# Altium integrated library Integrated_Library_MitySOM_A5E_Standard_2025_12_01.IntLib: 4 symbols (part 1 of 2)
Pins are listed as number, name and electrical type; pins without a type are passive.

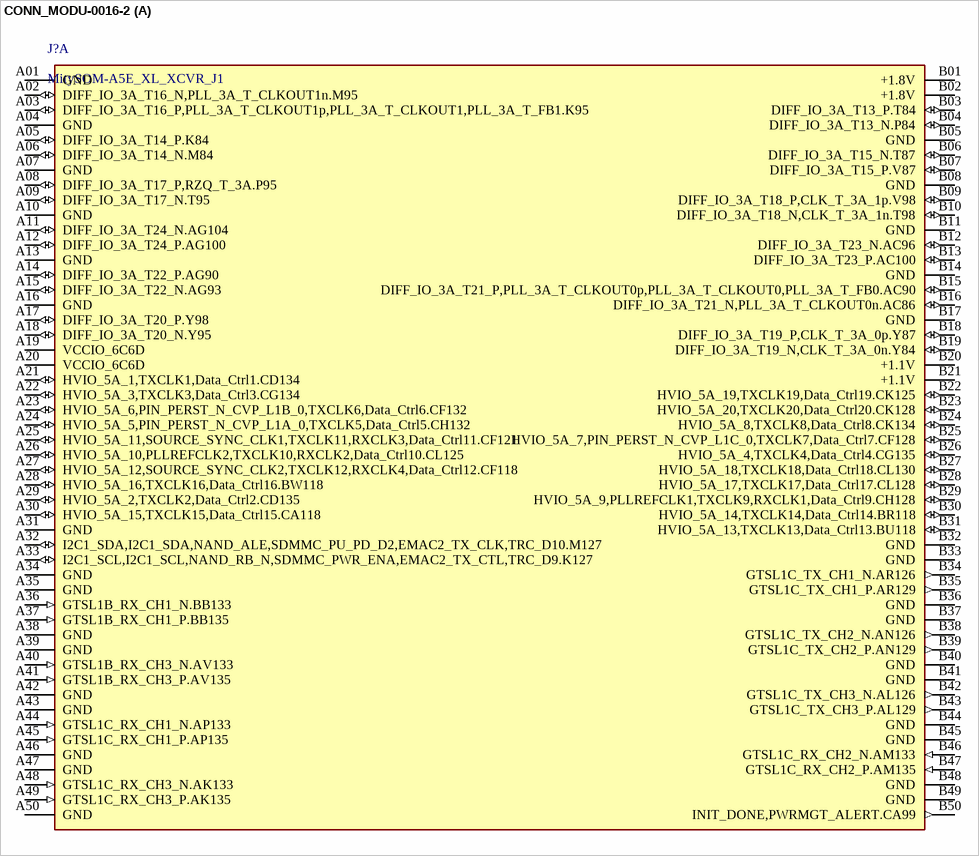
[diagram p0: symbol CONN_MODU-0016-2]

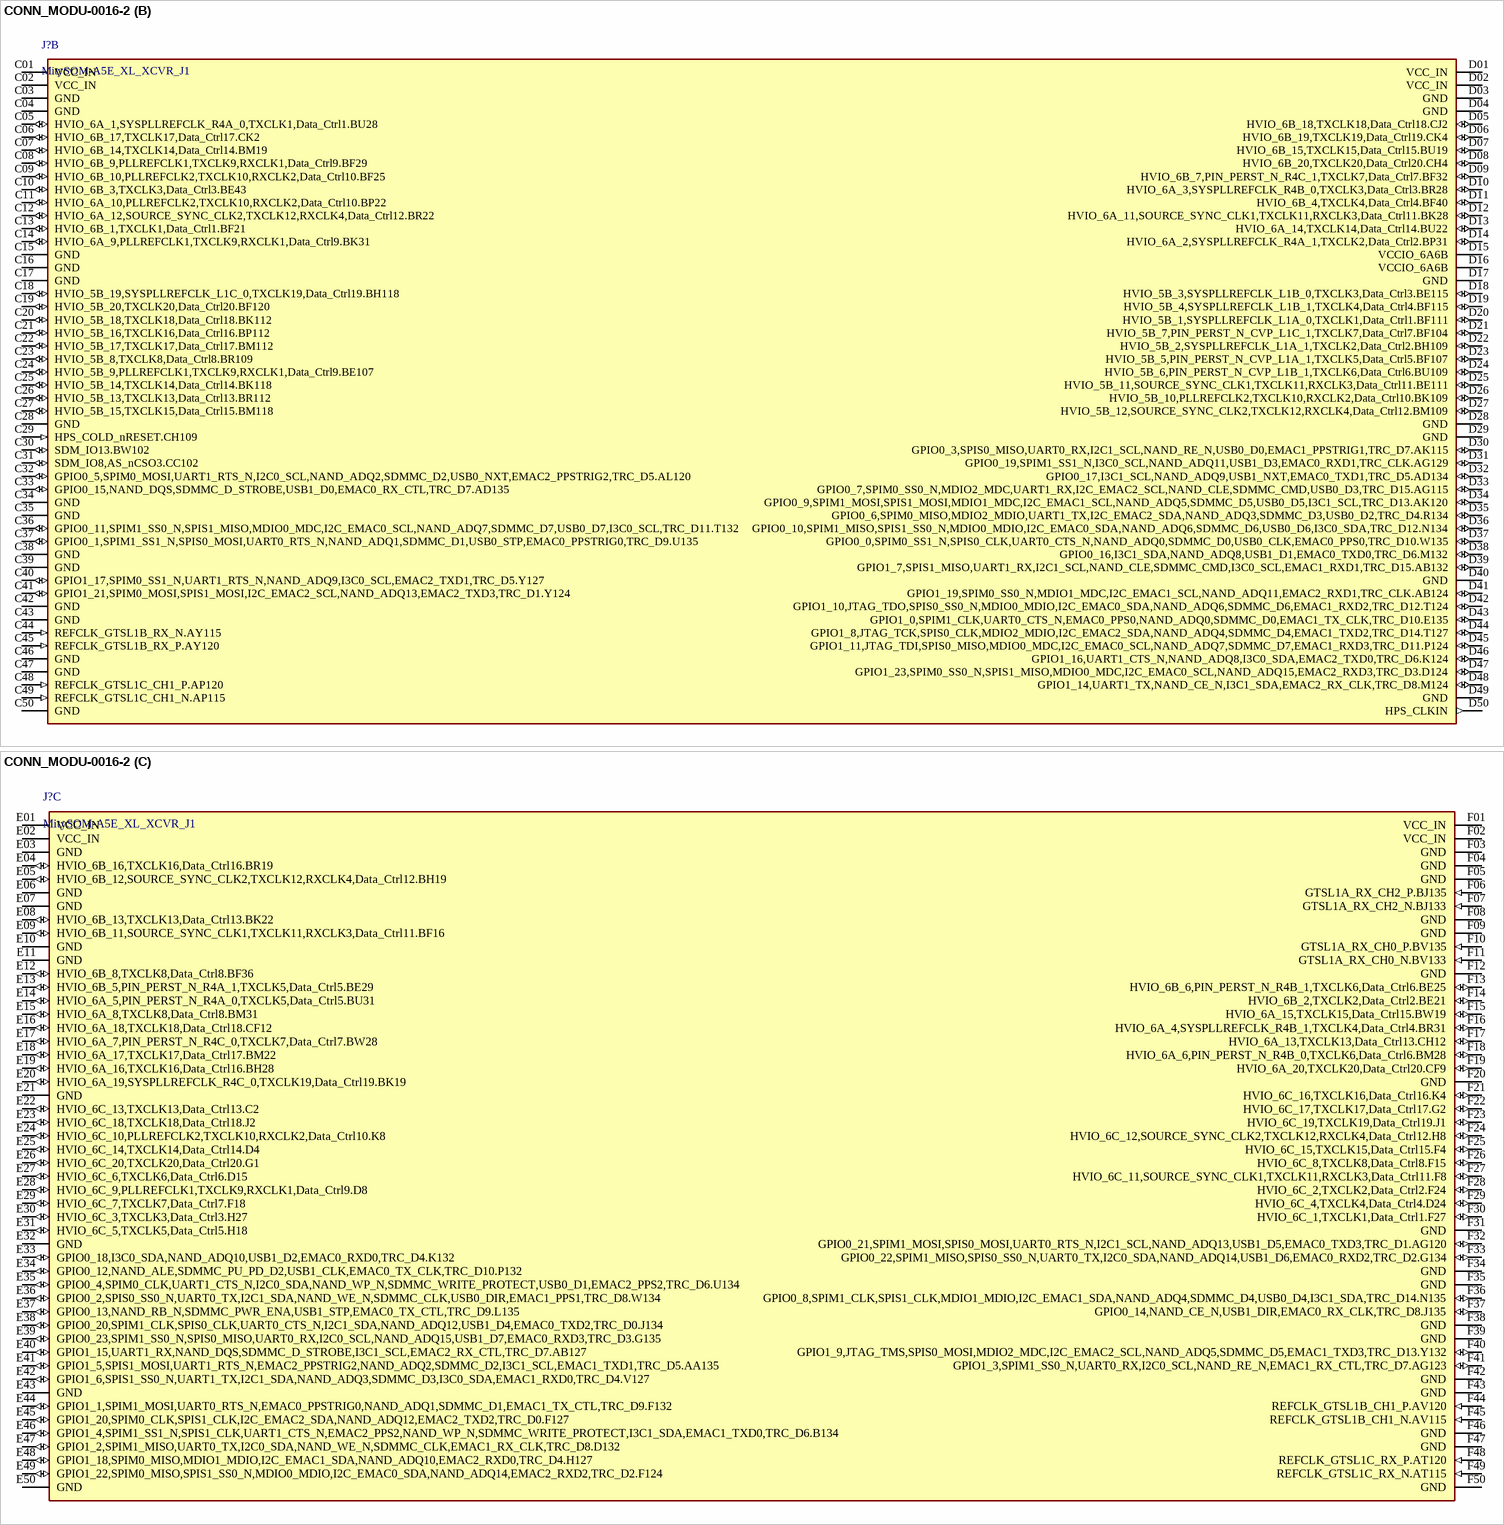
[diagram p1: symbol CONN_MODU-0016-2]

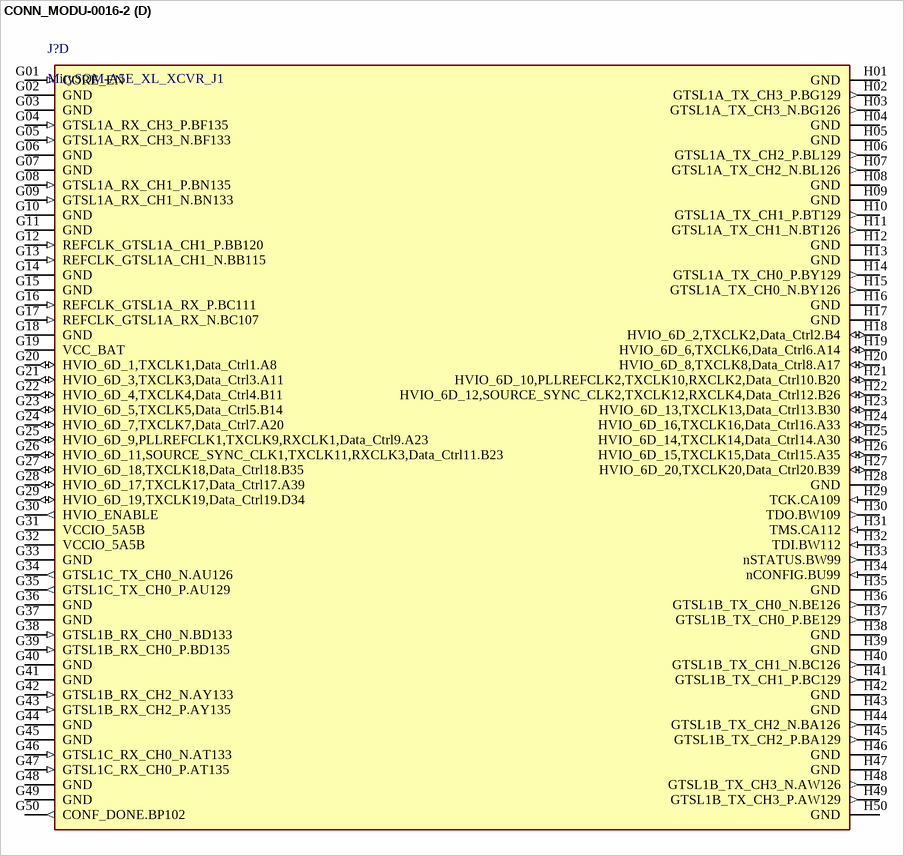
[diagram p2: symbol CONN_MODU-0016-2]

## CONN_MODU-0016-2
designator J?, comment MitySOM-A5E_XL_XCVR_J1
MitySOM-A5E XL XCVR Interface Connector, J1 CONN HD ARRAY PLUG 400P SMD GOLD; Manuf 1_PN: SEAM-50-02.0-L-08-2-A-K-TR; Manuf 2_PN: SEAM-50-02.0-S-08-2-A-K-TR; Manuf 1: Samtec; CLPN: 13059; Angle: Vertical
footprint SEAM-50-02.0-S-08-2-A-K-TR_MitySOM_A5E_J1 (CONN ARRAY SOCKET 400 POS SMD, with mechanical guidelines MitySOM-A5E J1/J2)
part A pins: A01 GND (power), A02 DIFF_IO_3A_T16_N,PLL_3A_T_CLKOUT1n.M95 (io), A03 DIFF_IO_3A_T16_P,PLL_3A_T_CLKOUT1p,PLL_3A_T_CLKOUT1,PLL_3A_T_FB1.K95 (io), A04 GND (power), A05 DIFF_IO_3A_T14_P.K84 (io), A06 DIFF_IO_3A_T14_N.M84 (io), A07 GND (power), A08 DIFF_IO_3A_T17_P,RZQ_T_3A.P95 (io), A09 DIFF_IO_3A_T17_N.T95 (io), A10 GND (power), A11 DIFF_IO_3A_T24_N.AG104 (io), A12 DIFF_IO_3A_T24_P.AG100 (io), A13 GND (power), A14 DIFF_IO_3A_T22_P.AG90 (io), A15 DIFF_IO_3A_T22_N.AG93 (io), A16 GND (power), A17 DIFF_IO_3A_T20_P.Y98 (io), A18 DIFF_IO_3A_T20_N.Y95 (io), A19 VCCIO_6C6D (power), A20 VCCIO_6C6D (power), A21 HVIO_5A_1,TXCLK1,Data_Ctrl1.CD134 (io), A22 HVIO_5A_3,TXCLK3,Data_Ctrl3.CG134 (io), A23 HVIO_5A_6,PIN_PERST_N_CVP_L1B_0,TXCLK6,Data_Ctrl6.CF132 (io), A24 HVIO_5A_5,PIN_PERST_N_CVP_L1A_0,TXCLK5,Data_Ctrl5.CH132 (io), A25 HVIO_5A_11,SOURCE_SYNC_CLK1,TXCLK11,RXCLK3,Data_Ctrl11.CF121 (io), A26 HVIO_5A_10,PLLREFCLK2,TXCLK10,RXCLK2,Data_Ctrl10.CL125 (io), A27 HVIO_5A_12,SOURCE_SYNC_CLK2,TXCLK12,RXCLK4,Data_Ctrl12.CF118 (io), A28 HVIO_5A_16,TXCLK16,Data_Ctrl16.BW118 (io), A29 HVIO_5A_2,TXCLK2,Data_Ctrl2.CD135 (io), A30 HVIO_5A_15,TXCLK15,Data_Ctrl15.CA118 (io), A31 GND (power), A32 I2C1_SDA,I2C1_SDA,NAND_ALE,SDMMC_PU_PD_D2,EMAC2_TX_CLK,TRC_D10.M127 (io), A33 I2C1_SCL,I2C1_SCL,NAND_RB_N,SDMMC_PWR_ENA,EMAC2_TX_CTL,TRC_D9.K127 (io), A34 GND (power), A35 GND (power), A36 GTSL1B_RX_CH1_N.BB133 (in), A37 GTSL1B_RX_CH1_P.BB135 (in), A38 GND (power), A39 GND (power), A40 GTSL1B_RX_CH3_N.AV133 (in), A41 GTSL1B_RX_CH3_P.AV135 (in), A42 GND (power), A43 GND (power), A44 GTSL1C_RX_CH1_N.AP133 (in), A45 GTSL1C_RX_CH1_P.AP135 (in), A46 GND (power), A47 GND (power), A48 GTSL1C_RX_CH3_N.AK133 (in), A49 GTSL1C_RX_CH3_P.AK135 (in), A50 GND (power), B01 +1.8V (power), B02 +1.8V (power), B03 DIFF_IO_3A_T13_P.T84 (io), B04 DIFF_IO_3A_T13_N.P84 (io), B05 GND (power), B06 DIFF_IO_3A_T15_N.T87 (io), B07 DIFF_IO_3A_T15_P.V87 (io), B08 GND (power), B09 DIFF_IO_3A_T18_P,CLK_T_3A_1p.V98 (io), B10 DIFF_IO_3A_T18_N,CLK_T_3A_1n.T98 (io), B11 GND (power), B12 DIFF_IO_3A_T23_N.AC96 (io), B13 DIFF_IO_3A_T23_P.AC100 (io), B14 GND (power), B15 DIFF_IO_3A_T21_P,PLL_3A_T_CLKOUT0p,PLL_3A_T_CLKOUT0,PLL_3A_T_FB0.AC90 (io), B16 DIFF_IO_3A_T21_N,PLL_3A_T_CLKOUT0n.AC86 (io), B17 GND (power), B18 DIFF_IO_3A_T19_P,CLK_T_3A_0p.Y87 (io), B19 DIFF_IO_3A_T19_N,CLK_T_3A_0n.Y84 (io), B20 +1.1V (power), B21 +1.1V (power), B22 HVIO_5A_19,TXCLK19,Data_Ctrl19.CK125 (io), B23 HVIO_5A_20,TXCLK20,Data_Ctrl20.CK128 (io), B24 HVIO_5A_8,TXCLK8,Data_Ctrl8.CK134 (io), B25 HVIO_5A_7,PIN_PERST_N_CVP_L1C_0,TXCLK7,Data_Ctrl7.CF128 (io), B26 HVIO_5A_4,TXCLK4,Data_Ctrl4.CG135 (io), B27 HVIO_5A_18,TXCLK18,Data_Ctrl18.CL130 (io), B28 HVIO_5A_17,TXCLK17,Data_Ctrl17.CL128 (io), B29 HVIO_5A_9,PLLREFCLK1,TXCLK9,RXCLK1,Data_Ctrl9.CH128 (io), B30 HVIO_5A_14,TXCLK14,Data_Ctrl14.BR118 (io), B31 HVIO_5A_13,TXCLK13,Data_Ctrl13.BU118 (io), B32 GND (power), B33 GND (power), B34 GTSL1C_TX_CH1_N.AR126 (out), B35 GTSL1C_TX_CH1_P.AR129 (out), B36 GND (power), B37 GND (power), B38 GTSL1C_TX_CH2_N.AN126 (out), B39 GTSL1C_TX_CH2_P.AN129 (out), B40 GND (power), B41 GND (power), B42 GTSL1C_TX_CH3_N.AL126 (out), B43 GTSL1C_TX_CH3_P.AL129 (out), B44 GND (power), B45 GND (power), B46 GTSL1C_RX_CH2_N.AM133 (in), B47 GTSL1C_RX_CH2_P.AM135 (in), B48 GND (power), B49 GND (power), B50 INIT_DONE,PWRMGT_ALERT.CA99 (out)
part B pins: C01 VCC_IN (power), C02 VCC_IN (power), C03 GND (power), C04 GND (power), C05 HVIO_6A_1,SYSPLLREFCLK_R4A_0,TXCLK1,Data_Ctrl1.BU28 (io), C06 HVIO_6B_17,TXCLK17,Data_Ctrl17.CK2 (io), C07 HVIO_6B_14,TXCLK14,Data_Ctrl14.BM19 (io), C08 HVIO_6B_9,PLLREFCLK1,TXCLK9,RXCLK1,Data_Ctrl9.BF29 (io), C09 HVIO_6B_10,PLLREFCLK2,TXCLK10,RXCLK2,Data_Ctrl10.BF25 (io), C10 HVIO_6B_3,TXCLK3,Data_Ctrl3.BE43 (io), C11 HVIO_6A_10,PLLREFCLK2,TXCLK10,RXCLK2,Data_Ctrl10.BP22 (io), C12 HVIO_6A_12,SOURCE_SYNC_CLK2,TXCLK12,RXCLK4,Data_Ctrl12.BR22 (io), C13 HVIO_6B_1,TXCLK1,Data_Ctrl1.BF21 (io), C14 HVIO_6A_9,PLLREFCLK1,TXCLK9,RXCLK1,Data_Ctrl9.BK31 (io), C15 GND (power), C16 GND (power), C17 GND (power), C18 HVIO_5B_19,SYSPLLREFCLK_L1C_0,TXCLK19,Data_Ctrl19.BH118 (io), C19 HVIO_5B_20,TXCLK20,Data_Ctrl20.BF120 (io), C20 HVIO_5B_18,TXCLK18,Data_Ctrl18.BK112 (io), C21 HVIO_5B_16,TXCLK16,Data_Ctrl16.BP112 (io), C22 HVIO_5B_17,TXCLK17,Data_Ctrl17.BM112 (io), C23 HVIO_5B_8,TXCLK8,Data_Ctrl8.BR109 (io), C24 HVIO_5B_9,PLLREFCLK1,TXCLK9,RXCLK1,Data_Ctrl9.BE107 (io), C25 HVIO_5B_14,TXCLK14,Data_Ctrl14.BK118 (io), C26 HVIO_5B_13,TXCLK13,Data_Ctrl13.BR112 (io), C27 HVIO_5B_15,TXCLK15,Data_Ctrl15.BM118 (io), C28 GND (power), C29 HPS_COLD_nRESET.CH109 (in), C30 SDM_IO13.BW102 (io), C31 SDM_IO8,AS_nCSO3.CC102 (io), C32 GPIO0_5,SPIM0_MOSI,UART1_RTS_N,I2C0_SCL,NAND_ADQ2,SDMMC_D2,USB0_NXT,EMAC2_PPSTRIG2,TRC_D5.AL120 (io), C33 GPIO0_15,NAND_DQS,SDMMC_D_STROBE,USB1_D0,EMAC0_RX_CTL,TRC_D7.AD135 (io), C34 GND (power), C35 GND (power), C36 GPIO0_11,SPIM1_SS0_N,SPIS1_MISO,MDIO0_MDC,I2C_EMAC0_SCL,NAND_ADQ7,SDMMC_D7,USB0_D7,I3C0_SCL,TRC_D11.T132 (io), C37 GPIO0_1,SPIM1_SS1_N,SPIS0_MOSI,UART0_RTS_N,NAND_ADQ1,SDMMC_D1,USB0_STP,EMAC0_PPSTRIG0,TRC_D9.U135 (io), C38 GND (power), C39 GND (power), C40 GPIO1_17,SPIM0_SS1_N,UART1_RTS_N,NAND_ADQ9,I3C0_SCL,EMAC2_TXD1,TRC_D5.Y127 (io), C41 GPIO1_21,SPIM0_MOSI,SPIS1_MOSI,I2C_EMAC2_SCL,NAND_ADQ13,EMAC2_TXD3,TRC_D1.Y124 (io), C42 GND (power), C43 GND (power), C44 REFCLK_GTSL1B_RX_N.AY115 (in), C45 REFCLK_GTSL1B_RX_P.AY120 (in), C46 GND (power), C47 GND (power), C48 REFCLK_GTSL1C_CH1_P.AP120 (in), C49 REFCLK_GTSL1C_CH1_N.AP115 (in), C50 GND (power), D01 VCC_IN (power), D02 VCC_IN (power), D03 GND (power), D04 GND (power), D05 HVIO_6B_18,TXCLK18,Data_Ctrl18.CJ2 (io), D06 HVIO_6B_19,TXCLK19,Data_Ctrl19.CK4 (io), D07 HVIO_6B_15,TXCLK15,Data_Ctrl15.BU19 (io), D08 HVIO_6B_20,TXCLK20,Data_Ctrl20.CH4 (io), D09 HVIO_6B_7,PIN_PERST_N_R4C_1,TXCLK7,Data_Ctrl7.BF32 (io), D10 HVIO_6A_3,SYSPLLREFCLK_R4B_0,TXCLK3,Data_Ctrl3.BR28 (io), D11 HVIO_6B_4,TXCLK4,Data_Ctrl4.BF40 (io), D12 HVIO_6A_11,SOURCE_SYNC_CLK1,TXCLK11,RXCLK3,Data_Ctrl11.BK28 (io), D13 HVIO_6A_14,TXCLK14,Data_Ctrl14.BU22 (io), D14 HVIO_6A_2,SYSPLLREFCLK_R4A_1,TXCLK2,Data_Ctrl2.BP31 (io), D15 VCCIO_6A6B (power), D16 VCCIO_6A6B (power), D17 GND (power), D18 HVIO_5B_3,SYSPLLREFCLK_L1B_0,TXCLK3,Data_Ctrl3.BE115 (io), D19 HVIO_5B_4,SYSPLLREFCLK_L1B_1,TXCLK4,Data_Ctrl4.BF115 (io), D20 HVIO_5B_1,SYSPLLREFCLK_L1A_0,TXCLK1,Data_Ctrl1.BF111 (io), D21 HVIO_5B_7,PIN_PERST_N_CVP_L1C_1,TXCLK7,Data_Ctrl7.BF104 (io), D22 HVIO_5B_2,SYSPLLREFCLK_L1A_1,TXCLK2,Data_Ctrl2.BH109 (io), D23 HVIO_5B_5,PIN_PERST_N_CVP_L1A_1,TXCLK5,Data_Ctrl5.BF107 (io), D24 HVIO_5B_6,PIN_PERST_N_CVP_L1B_1,TXCLK6,Data_Ctrl6.BU109 (io), D25 HVIO_5B_11,SOURCE_SYNC_CLK1,TXCLK11,RXCLK3,Data_Ctrl11.BE111 (io), D26 HVIO_5B_10,PLLREFCLK2,TXCLK10,RXCLK2,Data_Ctrl10.BK109 (io), D27 HVIO_5B_12,SOURCE_SYNC_CLK2,TXCLK12,RXCLK4,Data_Ctrl12.BM109 (io), D28 GND (power), D29 GND (power), D30 GPIO0_3,SPIS0_MISO,UART0_RX,I2C1_SCL,NAND_RE_N,USB0_D0,EMAC1_PPSTRIG1,TRC_D7.AK115 (io), D31 GPIO0_19,SPIM1_SS1_N,I3C0_SCL,NAND_ADQ11,USB1_D3,EMAC0_RXD1,TRC_CLK.AG129 (io), D32 GPIO0_17,I3C1_SCL,NAND_ADQ9,USB1_NXT,EMAC0_TXD1,TRC_D5.AD134 (io), D33 GPIO0_7,SPIM0_SS0_N,MDIO2_MDC,UART1_RX,I2C_EMAC2_SCL,NAND_CLE,SDMMC_CMD,USB0_D3,TRC_D15.AG115 (io), D34 GPIO0_9,SPIM1_MOSI,SPIS1_MOSI,MDIO1_MDC,I2C_EMAC1_SCL,NAND_ADQ5,SDMMC_D5,USB0_D5,I3C1_SCL,TRC_D13.AK120 (io), D35 GPIO0_6,SPIM0_MISO,MDIO2_MDIO,UART1_TX,I2C_EMAC2_SDA,NAND_ADQ3,SDMMC_D3,USB0_D2,TRC_D4.R134 (io), D36 GPIO0_10,SPIM1_MISO,SPIS1_SS0_N,MDIO0_MDIO,I2C_EMAC0_SDA,NAND_ADQ6,SDMMC_D6,USB0_D6,I3C0_SDA,TRC_D12.N134 (io), D37 GPIO0_0,SPIM0_SS1_N,SPIS0_CLK,UART0_CTS_N,NAND_ADQ0,SDMMC_D0,USB0_CLK,EMAC0_PPS0,TRC_D10.W135 (io), D38 GPIO0_16,I3C1_SDA,NAND_ADQ8,USB1_D1,EMAC0_TXD0,TRC_D6.M132 (io), D39 GPIO1_7,SPIS1_MISO,UART1_RX,I2C1_SCL,NAND_CLE,SDMMC_CMD,I3C0_SCL,EMAC1_RXD1,TRC_D15.AB132 (io), D40 GND (power), D41 GPIO1_19,SPIM0_SS0_N,MDIO1_MDC,I2C_EMAC1_SCL,NAND_ADQ11,EMAC2_RXD1,TRC_CLK.AB124 (io), D42 GPIO1_10,JTAG_TDO,SPIS0_SS0_N,MDIO0_MDIO,I2C_EMAC0_SDA,NAND_ADQ6,SDMMC_D6,EMAC1_RXD2,TRC_D12.T124 (io), D43 GPIO1_0,SPIM1_CLK,UART0_CTS_N,EMAC0_PPS0,NAND_ADQ0,SDMMC_D0,EMAC1_TX_CLK,TRC_D10.E135 (io), D44 GPIO1_8,JTAG_TCK,SPIS0_CLK,MDIO2_MDIO,I2C_EMAC2_SDA,NAND_ADQ4,SDMMC_D4,EMAC1_TXD2,TRC_D14.T127 (io), D45 GPIO1_11,JTAG_TDI,SPIS0_MISO,MDIO0_MDC,I2C_EMAC0_SCL,NAND_ADQ7,SDMMC_D7,EMAC1_RXD3,TRC_D11.P124 (io), D46 GPIO1_16,UART1_CTS_N,NAND_ADQ8,I3C0_SDA,EMAC2_TXD0,TRC_D6.K124 (io), D47 GPIO1_23,SPIM0_SS0_N,SPIS1_MISO,MDIO0_MDC,I2C_EMAC0_SCL,NAND_ADQ15,EMAC2_RXD3,TRC_D3.D124 (io), D48 GPIO1_14,UART1_TX,NAND_CE_N,I3C1_SDA,EMAC2_RX_CLK,TRC_D8.M124 (io), D49 GND (power), D50 HPS_CLKIN (out)
part C pins: E01 VCC_IN (power), E02 VCC_IN (power), E03 GND (power), E04 HVIO_6B_16,TXCLK16,Data_Ctrl16.BR19 (io), E05 HVIO_6B_12,SOURCE_SYNC_CLK2,TXCLK12,RXCLK4,Data_Ctrl12.BH19 (io), E06 GND (power), E07 GND (power), E08 HVIO_6B_13,TXCLK13,Data_Ctrl13.BK22 (io), E09 HVIO_6B_11,SOURCE_SYNC_CLK1,TXCLK11,RXCLK3,Data_Ctrl11.BF16 (io), E10 GND (power), E11 GND (power), E12 HVIO_6B_8,TXCLK8,Data_Ctrl8.BF36 (io), E13 HVIO_6B_5,PIN_PERST_N_R4A_1,TXCLK5,Data_Ctrl5.BE29 (io), E14 HVIO_6A_5,PIN_PERST_N_R4A_0,TXCLK5,Data_Ctrl5.BU31 (io), E15 HVIO_6A_8,TXCLK8,Data_Ctrl8.BM31 (io), E16 HVIO_6A_18,TXCLK18,Data_Ctrl18.CF12 (io), E17 HVIO_6A_7,PIN_PERST_N_R4C_0,TXCLK7,Data_Ctrl7.BW28 (io), E18 HVIO_6A_17,TXCLK17,Data_Ctrl17.BM22 (io), E19 HVIO_6A_16,TXCLK16,Data_Ctrl16.BH28 (io), E20 HVIO_6A_19,SYSPLLREFCLK_R4C_0,TXCLK19,Data_Ctrl19.BK19 (io), E21 GND (power), E22 HVIO_6C_13,TXCLK13,Data_Ctrl13.C2 (io), E23 HVIO_6C_18,TXCLK18,Data_Ctrl18.J2 (io), E24 HVIO_6C_10,PLLREFCLK2,TXCLK10,RXCLK2,Data_Ctrl10.K8 (io), E25 HVIO_6C_14,TXCLK14,Data_Ctrl14.D4 (io), E26 HVIO_6C_20,TXCLK20,Data_Ctrl20.G1 (io), E27 HVIO_6C_6,TXCLK6,Data_Ctrl6.D15 (io), E28 HVIO_6C_9,PLLREFCLK1,TXCLK9,RXCLK1,Data_Ctrl9.D8 (io), E29 HVIO_6C_7,TXCLK7,Data_Ctrl7.F18 (io), E30 HVIO_6C_3,TXCLK3,Data_Ctrl3.H27 (io), E31 HVIO_6C_5,TXCLK5,Data_Ctrl5.H18 (io), E32 GND (power), E33 GPIO0_18,I3C0_SDA,NAND_ADQ10,USB1_D2,EMAC0_RXD0,TRC_D4.K132 (io), E34 GPIO0_12,NAND_ALE,SDMMC_PU_PD_D2,USB1_CLK,EMAC0_TX_CLK,TRC_D10.P132 (io), E35 GPIO0_4,SPIM0_CLK,UART1_CTS_N,I2C0_SDA,NAND_WP_N,SDMMC_WRITE_PROTECT,USB0_D1,EMAC2_PPS2,TRC_D6.U134 (io), E36 GPIO0_2,SPIS0_SS0_N,UART0_TX,I2C1_SDA,NAND_WE_N,SDMMC_CLK,USB0_DIR,EMAC1_PPS1,TRC_D8.W134 (io), E37 GPIO0_13,NAND_RB_N,SDMMC_PWR_ENA,USB1_STP,EMAC0_TX_CTL,TRC_D9.L135 (io), E38 GPIO0_20,SPIM1_CLK,SPIS0_CLK,UART0_CTS_N,I2C1_SDA,NAND_ADQ12,USB1_D4,EMAC0_TXD2,TRC_D0.J134 (io), E39 GPIO0_23,SPIM1_SS0_N,SPIS0_MISO,UART0_RX,I2C0_SCL,NAND_ADQ15,USB1_D7,EMAC0_RXD3,TRC_D3.G135 (io), E40 GPIO1_15,UART1_RX,NAND_DQS,SDMMC_D_STROBE,I3C1_SCL,EMAC2_RX_CTL,TRC_D7.AB127 (io), E41 GPIO1_5,SPIS1_MOSI,UART1_RTS_N,EMAC2_PPSTRIG2,NAND_ADQ2,SDMMC_D2,I3C1_SCL,EMAC1_TXD1,TRC_D5.AA135 (io), E42 GPIO1_6,SPIS1_SS0_N,UART1_TX,I2C1_SDA,NAND_ADQ3,SDMMC_D3,I3C0_SDA,EMAC1_RXD0,TRC_D4.V127 (io), E43 GND (power), E44 GPIO1_1,SPIM1_MOSI,UART0_RTS_N,EMAC0_PPSTRIG0,NAND_ADQ1,SDMMC_D1,EMAC1_TX_CTL,TRC_D9.F132 (io), E45 GPIO1_20,SPIM0_CLK,SPIS1_CLK,I2C_EMAC2_SDA,NAND_ADQ12,EMAC2_TXD2,TRC_D0.F127 (io), E46 GPIO1_4,SPIM1_SS1_N,SPIS1_CLK,UART1_CTS_N,EMAC2_PPS2,NAND_WP_N,SDMMC_WRITE_PROTECT,I3C1_SDA,EMAC1_TXD0,TRC_D6.B134 (io), E47 GPIO1_2,SPIM1_MISO,UART0_TX,I2C0_SDA,NAND_WE_N,SDMMC_CLK,EMAC1_RX_CLK,TRC_D8.D132 (io), E48 GPIO1_18,SPIM0_MISO,MDIO1_MDIO,I2C_EMAC1_SDA,NAND_ADQ10,EMAC2_RXD0,TRC_D4.H127 (io), E49 GPIO1_22,SPIM0_MISO,SPIS1_SS0_N,MDIO0_MDIO,I2C_EMAC0_SDA,NAND_ADQ14,EMAC2_RXD2,TRC_D2.F124 (io), E50 GND (power), F01 VCC_IN (power), F02 VCC_IN (power), F03 GND (power), F04 GND (power), F05 GND (power), F06 GTSL1A_RX_CH2_P.BJ135 (in), F07 GTSL1A_RX_CH2_N.BJ133 (in), F08 GND (power), F09 GND (power), F10 GTSL1A_RX_CH0_P.BV135 (in), F11 GTSL1A_RX_CH0_N.BV133 (in), F12 GND (power), F13 HVIO_6B_6,PIN_PERST_N_R4B_1,TXCLK6,Data_Ctrl6.BE25 (io), F14 HVIO_6B_2,TXCLK2,Data_Ctrl2.BE21 (io), F15 HVIO_6A_15,TXCLK15,Data_Ctrl15.BW19 (io), F16 HVIO_6A_4,SYSPLLREFCLK_R4B_1,TXCLK4,Data_Ctrl4.BR31 (io), F17 HVIO_6A_13,TXCLK13,Data_Ctrl13.CH12 (io), F18 HVIO_6A_6,PIN_PERST_N_R4B_0,TXCLK6,Data_Ctrl6.BM28 (io), F19 HVIO_6A_20,TXCLK20,Data_Ctrl20.CF9 (io), F20 GND (power), F21 HVIO_6C_16,TXCLK16,Data_Ctrl16.K4 (io), F22 HVIO_6C_17,TXCLK17,Data_Ctrl17.G2 (io), F23 HVIO_6C_19,TXCLK19,Data_Ctrl19.J1 (io), F24 HVIO_6C_12,SOURCE_SYNC_CLK2,TXCLK12,RXCLK4,Data_Ctrl12.H8 (io), F25 HVIO_6C_15,TXCLK15,Data_Ctrl15.F4 (io), F26 HVIO_6C_8,TXCLK8,Data_Ctrl8.F15 (io), F27 HVIO_6C_11,SOURCE_SYNC_CLK1,TXCLK11,RXCLK3,Data_Ctrl11.F8 (io), F28 HVIO_6C_2,TXCLK2,Data_Ctrl2.F24 (io), F29 HVIO_6C_4,TXCLK4,Data_Ctrl4.D24 (io), F30 HVIO_6C_1,TXCLK1,Data_Ctrl1.F27 (io), F31 GND (power), F32 GPIO0_21,SPIM1_MOSI,SPIS0_MOSI,UART0_RTS_N,I2C1_SCL,NAND_ADQ13,USB1_D5,EMAC0_TXD3,TRC_D1.AG120 (io), F33 GPIO0_22,SPIM1_MISO,SPIS0_SS0_N,UART0_TX,I2C0_SDA,NAND_ADQ14,USB1_D6,EMAC0_RXD2,TRC_D2.G134 (io), F34 GND (power), F35 GND (power), F36 GPIO0_8,SPIM1_CLK,SPIS1_CLK,MDIO1_MDIO,I2C_EMAC1_SDA,NAND_ADQ4,SDMMC_D4,USB0_D4,I3C1_SDA,TRC_D14.N135 (io), F37 GPIO0_14,NAND_CE_N,USB1_DIR,EMAC0_RX_CLK,TRC_D8.J135 (io), F38 GND (power), F39 GND (power), F40 GPIO1_9,JTAG_TMS,SPIS0_MOSI,MDIO2_MDC,I2C_EMAC2_SCL,NAND_ADQ5,SDMMC_D5,EMAC1_TXD3,TRC_D13.Y132 (io), F41 GPIO1_3,SPIM1_SS0_N,UART0_RX,I2C0_SCL,NAND_RE_N,EMAC1_RX_CTL,TRC_D7.AG123 (io), F42 GND (power), F43 GND (power), F44 REFCLK_GTSL1B_CH1_P.AV120 (in), F45 REFCLK_GTSL1B_CH1_N.AV115 (in), F46 GND (power), F47 GND (power), F48 REFCLK_GTSL1C_RX_P.AT120 (in), F49 REFCLK_GTSL1C_RX_N.AT115 (in), F50 GND (power)
part D pins: G01 CORE_EN (in), G02 GND (power), G03 GND (power), G04 GTSL1A_RX_CH3_P.BF135 (in), G05 GTSL1A_RX_CH3_N.BF133 (in), G06 GND (power), G07 GND (power), G08 GTSL1A_RX_CH1_P.BN135 (in), G09 GTSL1A_RX_CH1_N.BN133 (in), G10 GND (power), G11 GND (power), G12 REFCLK_GTSL1A_CH1_P.BB120 (in), G13 REFCLK_GTSL1A_CH1_N.BB115 (in), G14 GND (power), G15 GND (power), G16 REFCLK_GTSL1A_RX_P.BC111 (in), G17 REFCLK_GTSL1A_RX_N.BC107 (in), G18 GND (power), G19 VCC_BAT (power), G20 HVIO_6D_1,TXCLK1,Data_Ctrl1.A8 (io), G21 HVIO_6D_3,TXCLK3,Data_Ctrl3.A11 (io), G22 HVIO_6D_4,TXCLK4,Data_Ctrl4.B11 (io), G23 HVIO_6D_5,TXCLK5,Data_Ctrl5.B14 (io), G24 HVIO_6D_7,TXCLK7,Data_Ctrl7.A20 (io), G25 HVIO_6D_9,PLLREFCLK1,TXCLK9,RXCLK1,Data_Ctrl9.A23 (io), G26 HVIO_6D_11,SOURCE_SYNC_CLK1,TXCLK11,RXCLK3,Data_Ctrl11.B23 (io), G27 HVIO_6D_18,TXCLK18,Data_Ctrl18.B35 (io), G28 HVIO_6D_17,TXCLK17,Data_Ctrl17.A39 (io), G29 HVIO_6D_19,TXCLK19,Data_Ctrl19.D34 (io), G30 HVIO_ENABLE (out), G31 VCCIO_5A5B (power), G32 VCCIO_5A5B (power), G33 GND (power), G34 GTSL1C_TX_CH0_N.AU126 (out), G35 GTSL1C_TX_CH0_P.AU129 (out), G36 GND (power), G37 GND (power), G38 GTSL1B_RX_CH0_N.BD133 (in), G39 GTSL1B_RX_CH0_P.BD135 (in), G40 GND (power), G41 GND (power), G42 GTSL1B_RX_CH2_N.AY133 (in), G43 GTSL1B_RX_CH2_P.AY135 (in), G44 GND (power), G45 GND (power), G46 GTSL1C_RX_CH0_N.AT133 (in), G47 GTSL1C_RX_CH0_P.AT135 (in), G48 GND (power), G49 GND (power), G50 CONF_DONE.BP102 (out), H01 GND (power), H02 GTSL1A_TX_CH3_P.BG129 (out), H03 GTSL1A_TX_CH3_N.BG126 (out), H04 GND (power), H05 GND (power), H06 GTSL1A_TX_CH2_P.BL129 (out), H07 GTSL1A_TX_CH2_N.BL126 (out), H08 GND (power), H09 GND (power), H10 GTSL1A_TX_CH1_P.BT129 (out), H11 GTSL1A_TX_CH1_N.BT126 (out), H12 GND (power), H13 GND (power), H14 GTSL1A_TX_CH0_P.BY129 (out), H15 GTSL1A_TX_CH0_N.BY126 (out), H16 GND (power), H17 GND (power), H18 HVIO_6D_2,TXCLK2,Data_Ctrl2.B4 (io), H19 HVIO_6D_6,TXCLK6,Data_Ctrl6.A14 (io), H20 HVIO_6D_8,TXCLK8,Data_Ctrl8.A17 (io), H21 HVIO_6D_10,PLLREFCLK2,TXCLK10,RXCLK2,Data_Ctrl10.B20 (io), H22 HVIO_6D_12,SOURCE_SYNC_CLK2,TXCLK12,RXCLK4,Data_Ctrl12.B26 (io), H23 HVIO_6D_13,TXCLK13,Data_Ctrl13.B30 (io), H24 HVIO_6D_16,TXCLK16,Data_Ctrl16.A33 (io), H25 HVIO_6D_14,TXCLK14,Data_Ctrl14.A30 (io), H26 HVIO_6D_15,TXCLK15,Data_Ctrl15.A35 (io), H27 HVIO_6D_20,TXCLK20,Data_Ctrl20.B39 (io), H28 GND (power), H29 TCK.CA109 (in), H30 TDO.BW109 (out), H31 TMS.CA112 (in), H32 TDI.BW112 (in), H33 nSTATUS.BW99 (out), H34 nCONFIG.BU99 (in), H35 GND (power), H36 GTSL1B_TX_CH0_N.BE126 (out), H37 GTSL1B_TX_CH0_P.BE129 (out), H38 GND (power), H39 GND (power), H40 GTSL1B_TX_CH1_N.BC126 (out), H41 GTSL1B_TX_CH1_P.BC129 (out), H42 GND (power), H43 GND (power), H44 GTSL1B_TX_CH2_N.BA126 (out), H45 GTSL1B_TX_CH2_P.BA129 (out), H46 GND (power), H47 GND (power), H48 GTSL1B_TX_CH3_N.AW126 (out), H49 GTSL1B_TX_CH3_P.AW129 (out), H50 GND (power)

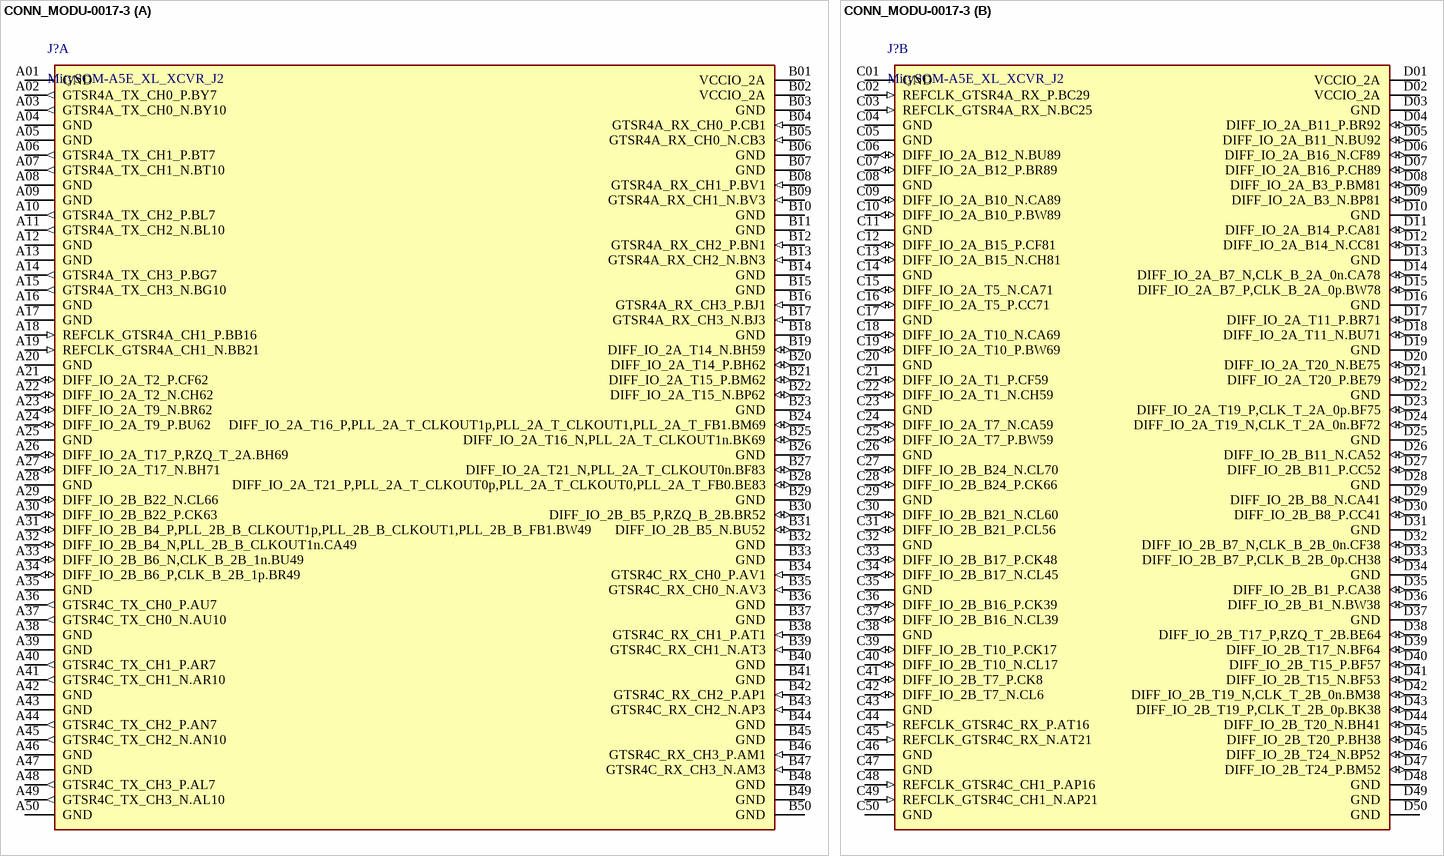
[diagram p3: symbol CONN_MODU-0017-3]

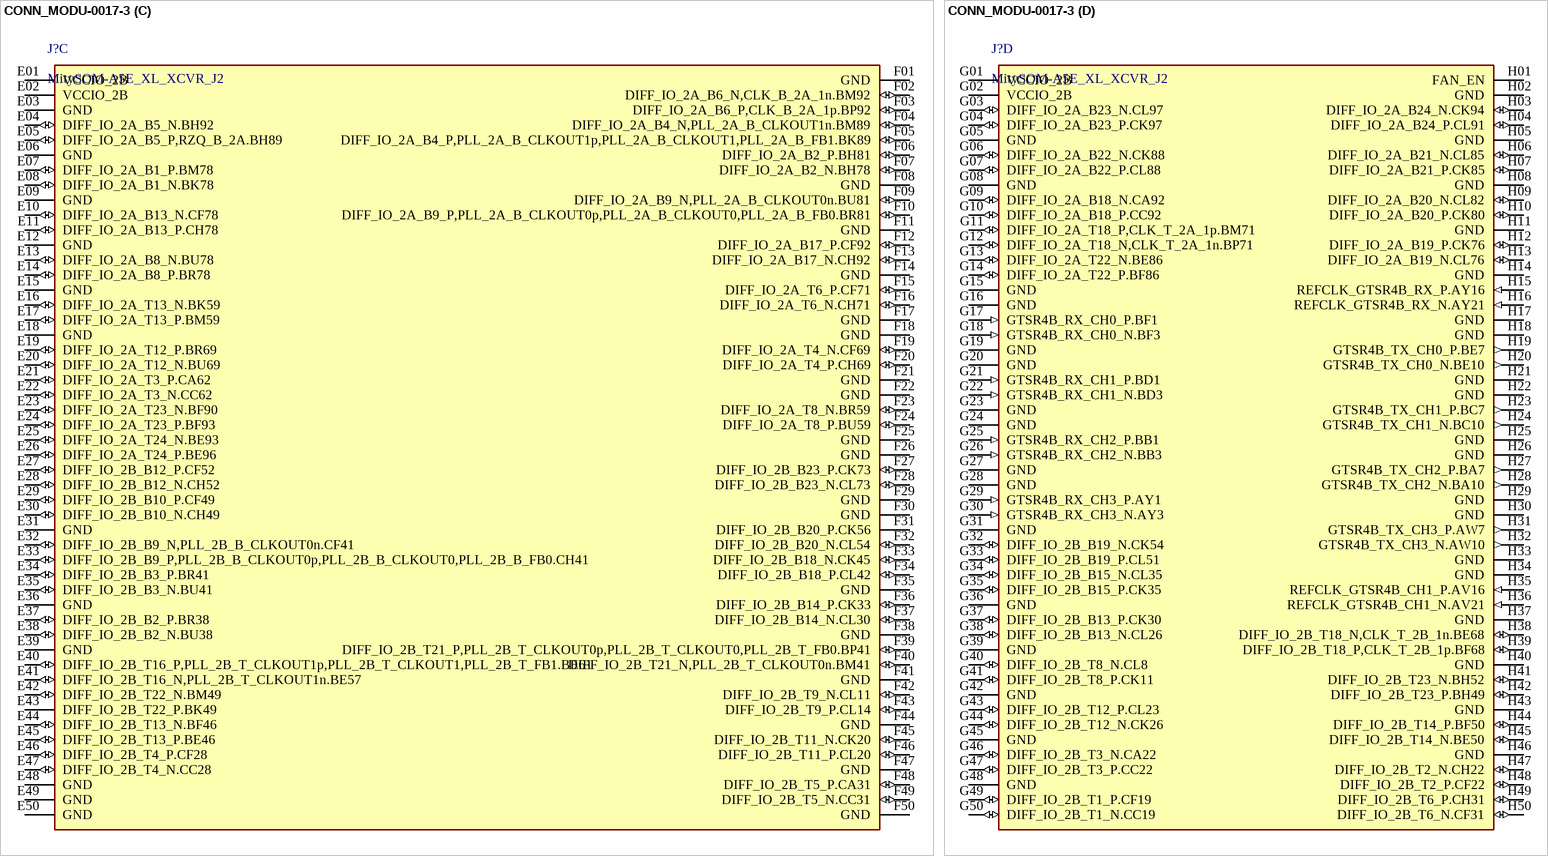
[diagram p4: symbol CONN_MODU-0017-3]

## CONN_MODU-0017-3
designator J?, comment MitySOM-A5E_XL_XCVR_J2
MitySOM-A5E  XL XCVR Interface Connector, J2, CONN HD ARRAY PLUG 400P SMD GOLD; Manuf 1: Samtec; Manuf 1_PN: SEAM-50-02.0-L-08-2-A-K-TR; Manuf 2_PN: SEAM-50-02.0-S-08-2-A-K-TR; Angle: Vertical; CLPN: 13059
footprint SEAM-50-02.0-S-08-2-A-K-TR (CONN ARRAY SOCKET 400 POS SMD)
part A pins: A01 GND (power), A02 GTSR4A_TX_CH0_P.BY7 (out), A03 GTSR4A_TX_CH0_N.BY10 (out), A04 GND (power), A05 GND (power), A06 GTSR4A_TX_CH1_P.BT7 (out), A07 GTSR4A_TX_CH1_N.BT10 (out), A08 GND (power), A09 GND (power), A10 GTSR4A_TX_CH2_P.BL7 (out), A11 GTSR4A_TX_CH2_N.BL10 (out), A12 GND (power), A13 GND (power), A14 GTSR4A_TX_CH3_P.BG7 (out), A15 GTSR4A_TX_CH3_N.BG10 (out), A16 GND (power), A17 GND (power), A18 REFCLK_GTSR4A_CH1_P.BB16 (in), A19 REFCLK_GTSR4A_CH1_N.BB21 (in), A20 GND (power), A21 DIFF_IO_2A_T2_P.CF62 (io), A22 DIFF_IO_2A_T2_N.CH62 (io), A23 DIFF_IO_2A_T9_N.BR62 (io), A24 DIFF_IO_2A_T9_P.BU62 (io), A25 GND (power), A26 DIFF_IO_2A_T17_P,RZQ_T_2A.BH69 (io), A27 DIFF_IO_2A_T17_N.BH71 (io), A28 GND (power), A29 DIFF_IO_2B_B22_N.CL66 (io), A30 DIFF_IO_2B_B22_P.CK63 (io), A31 DIFF_IO_2B_B4_P,PLL_2B_B_CLKOUT1p,PLL_2B_B_CLKOUT1,PLL_2B_B_FB1.BW49 (io), A32 DIFF_IO_2B_B4_N,PLL_2B_B_CLKOUT1n.CA49 (io), A33 DIFF_IO_2B_B6_N,CLK_B_2B_1n.BU49 (io), A34 DIFF_IO_2B_B6_P,CLK_B_2B_1p.BR49 (io), A35 GND (power), A36 GTSR4C_TX_CH0_P.AU7 (out), A37 GTSR4C_TX_CH0_N.AU10 (out), A38 GND (power), A39 GND (power), A40 GTSR4C_TX_CH1_P.AR7 (out), A41 GTSR4C_TX_CH1_N.AR10 (out), A42 GND (power), A43 GND (power), A44 GTSR4C_TX_CH2_P.AN7 (out), A45 GTSR4C_TX_CH2_N.AN10 (out), A46 GND (power), A47 GND (power), A48 GTSR4C_TX_CH3_P.AL7 (out), A49 GTSR4C_TX_CH3_N.AL10 (out), A50 GND (power), B01 VCCIO_2A (power), B02 VCCIO_2A (power), B03 GND (power), B04 GTSR4A_RX_CH0_P.CB1 (in), B05 GTSR4A_RX_CH0_N.CB3 (in), B06 GND (power), B07 GND (power), B08 GTSR4A_RX_CH1_P.BV1 (in), B09 GTSR4A_RX_CH1_N.BV3 (in), B10 GND (power), B11 GND (power), B12 GTSR4A_RX_CH2_P.BN1 (in), B13 GTSR4A_RX_CH2_N.BN3 (in), B14 GND (power), B15 GND (power), B16 GTSR4A_RX_CH3_P.BJ1 (in), B17 GTSR4A_RX_CH3_N.BJ3 (in), B18 GND (power), B19 DIFF_IO_2A_T14_N.BH59 (io), B20 DIFF_IO_2A_T14_P.BH62 (io), B21 DIFF_IO_2A_T15_P.BM62 (io), B22 DIFF_IO_2A_T15_N.BP62 (io), B23 GND (power), B24 DIFF_IO_2A_T16_P,PLL_2A_T_CLKOUT1p,PLL_2A_T_CLKOUT1,PLL_2A_T_FB1.BM69 (io), B25 DIFF_IO_2A_T16_N,PLL_2A_T_CLKOUT1n.BK69 (io), B26 GND (power), B27 DIFF_IO_2A_T21_N,PLL_2A_T_CLKOUT0n.BF83 (io), B28 DIFF_IO_2A_T21_P,PLL_2A_T_CLKOUT0p,PLL_2A_T_CLKOUT0,PLL_2A_T_FB0.BE83 (io), B29 GND (power), B30 DIFF_IO_2B_B5_P,RZQ_B_2B.BR52 (io), B31 DIFF_IO_2B_B5_N.BU52 (io), B32 GND (power), B33 GND (power), B34 GTSR4C_RX_CH0_P.AV1 (in), B35 GTSR4C_RX_CH0_N.AV3 (in), B36 GND (power), B37 GND (power), B38 GTSR4C_RX_CH1_P.AT1 (in), B39 GTSR4C_RX_CH1_N.AT3 (in), B40 GND (power), B41 GND (power), B42 GTSR4C_RX_CH2_P.AP1 (in), B43 GTSR4C_RX_CH2_N.AP3 (in), B44 GND (power), B45 GND (power), B46 GTSR4C_RX_CH3_P.AM1 (in), B47 GTSR4C_RX_CH3_N.AM3 (in), B48 GND (power), B49 GND (power), B50 GND (power)
part B pins: C01 GND (power), C02 REFCLK_GTSR4A_RX_P.BC29 (in), C03 REFCLK_GTSR4A_RX_N.BC25 (in), C04 GND (power), C05 GND (power), C06 DIFF_IO_2A_B12_N.BU89 (io), C07 DIFF_IO_2A_B12_P.BR89 (io), C08 GND (power), C09 DIFF_IO_2A_B10_N.CA89 (io), C10 DIFF_IO_2A_B10_P.BW89 (io), C11 GND (power), C12 DIFF_IO_2A_B15_P.CF81 (io), C13 DIFF_IO_2A_B15_N.CH81 (io), C14 GND (power), C15 DIFF_IO_2A_T5_N.CA71 (io), C16 DIFF_IO_2A_T5_P.CC71 (io), C17 GND (power), C18 DIFF_IO_2A_T10_N.CA69 (io), C19 DIFF_IO_2A_T10_P.BW69 (io), C20 GND (power), C21 DIFF_IO_2A_T1_P.CF59 (io), C22 DIFF_IO_2A_T1_N.CH59 (io), C23 GND (power), C24 DIFF_IO_2A_T7_N.CA59 (io), C25 DIFF_IO_2A_T7_P.BW59 (io), C26 GND (power), C27 DIFF_IO_2B_B24_N.CL70 (io), C28 DIFF_IO_2B_B24_P.CK66 (io), C29 GND (power), C30 DIFF_IO_2B_B21_N.CL60 (io), C31 DIFF_IO_2B_B21_P.CL56 (io), C32 GND (power), C33 DIFF_IO_2B_B17_P.CK48 (io), C34 DIFF_IO_2B_B17_N.CL45 (io), C35 GND (power), C36 DIFF_IO_2B_B16_P.CK39 (io), C37 DIFF_IO_2B_B16_N.CL39 (io), C38 GND (power), C39 DIFF_IO_2B_T10_P.CK17 (io), C40 DIFF_IO_2B_T10_N.CL17 (io), C41 DIFF_IO_2B_T7_P.CK8 (io), C42 DIFF_IO_2B_T7_N.CL6 (io), C43 GND (power), C44 REFCLK_GTSR4C_RX_P.AT16 (in), C45 REFCLK_GTSR4C_RX_N.AT21 (in), C46 GND (power), C47 GND (power), C48 REFCLK_GTSR4C_CH1_P.AP16 (in), C49 REFCLK_GTSR4C_CH1_N.AP21 (in), C50 GND (power), D01 VCCIO_2A (power), D02 VCCIO_2A (power), D03 GND (power), D04 DIFF_IO_2A_B11_P.BR92 (io), D05 DIFF_IO_2A_B11_N.BU92 (io), D06 DIFF_IO_2A_B16_N.CF89 (io), D07 DIFF_IO_2A_B16_P.CH89 (io), D08 DIFF_IO_2A_B3_P.BM81 (io), D09 DIFF_IO_2A_B3_N.BP81 (io), D10 GND (power), D11 DIFF_IO_2A_B14_P.CA81 (io), D12 DIFF_IO_2A_B14_N.CC81 (io), D13 GND (power), D14 DIFF_IO_2A_B7_N,CLK_B_2A_0n.CA78 (io), D15 DIFF_IO_2A_B7_P,CLK_B_2A_0p.BW78 (io), D16 GND (power), D17 DIFF_IO_2A_T11_P.BR71 (io), D18 DIFF_IO_2A_T11_N.BU71 (io), D19 GND (power), D20 DIFF_IO_2A_T20_N.BE75 (io), D21 DIFF_IO_2A_T20_P.BE79 (io), D22 GND (power), D23 DIFF_IO_2A_T19_P,CLK_T_2A_0p.BF75 (io), D24 DIFF_IO_2A_T19_N,CLK_T_2A_0n.BF72 (io), D25 GND (power), D26 DIFF_IO_2B_B11_N.CA52 (io), D27 DIFF_IO_2B_B11_P.CC52 (io), D28 GND (power), D29 DIFF_IO_2B_B8_N.CA41 (io), D30 DIFF_IO_2B_B8_P.CC41 (io), D31 GND (power), D32 DIFF_IO_2B_B7_N,CLK_B_2B_0n.CF38 (io), D33 DIFF_IO_2B_B7_P,CLK_B_2B_0p.CH38 (io), D34 GND (power), D35 DIFF_IO_2B_B1_P.CA38 (io), D36 DIFF_IO_2B_B1_N.BW38 (io), D37 GND (power), D38 DIFF_IO_2B_T17_P,RZQ_T_2B.BE64 (io), D39 DIFF_IO_2B_T17_N.BF64 (io), D40 DIFF_IO_2B_T15_P.BF57 (io), D41 DIFF_IO_2B_T15_N.BF53 (io), D42 DIFF_IO_2B_T19_N,CLK_T_2B_0n.BM38 (io), D43 DIFF_IO_2B_T19_P,CLK_T_2B_0p.BK38 (io), D44 DIFF_IO_2B_T20_N.BH41 (io), D45 DIFF_IO_2B_T20_P.BH38 (io), D46 DIFF_IO_2B_T24_N.BP52 (io), D47 DIFF_IO_2B_T24_P.BM52 (io), D48 GND (power), D49 GND (power), D50 GND (power)
part C pins: E01 VCCIO_2B (power), E02 VCCIO_2B (power), E03 GND (power), E04 DIFF_IO_2A_B5_N.BH92 (io), E05 DIFF_IO_2A_B5_P,RZQ_B_2A.BH89 (io), E06 GND (power), E07 DIFF_IO_2A_B1_P.BM78 (io), E08 DIFF_IO_2A_B1_N.BK78 (io), E09 GND (power), E10 DIFF_IO_2A_B13_N.CF78 (io), E11 DIFF_IO_2A_B13_P.CH78 (io), E12 GND (power), E13 DIFF_IO_2A_B8_N.BU78 (io), E14 DIFF_IO_2A_B8_P.BR78 (io), E15 GND (power), E16 DIFF_IO_2A_T13_N.BK59 (io), E17 DIFF_IO_2A_T13_P.BM59 (io), E18 GND (power), E19 DIFF_IO_2A_T12_P.BR69 (io), E20 DIFF_IO_2A_T12_N.BU69 (io), E21 DIFF_IO_2A_T3_P.CA62 (io), E22 DIFF_IO_2A_T3_N.CC62 (io), E23 DIFF_IO_2A_T23_N.BF90 (io), E24 DIFF_IO_2A_T23_P.BF93 (io), E25 DIFF_IO_2A_T24_N.BE93 (io), E26 DIFF_IO_2A_T24_P.BE96 (io), E27 DIFF_IO_2B_B12_P.CF52 (io), E28 DIFF_IO_2B_B12_N.CH52 (io), E29 DIFF_IO_2B_B10_P.CF49 (io), E30 DIFF_IO_2B_B10_N.CH49 (io), E31 GND (power), E32 DIFF_IO_2B_B9_N,PLL_2B_B_CLKOUT0n.CF41 (io), E33 DIFF_IO_2B_B9_P,PLL_2B_B_CLKOUT0p,PLL_2B_B_CLKOUT0,PLL_2B_B_FB0.CH41 (io), E34 DIFF_IO_2B_B3_P.BR41 (io), E35 DIFF_IO_2B_B3_N.BU41 (io), E36 GND (power), E37 DIFF_IO_2B_B2_P.BR38 (io), E38 DIFF_IO_2B_B2_N.BU38 (io), E39 GND (power), E40 DIFF_IO_2B_T16_P,PLL_2B_T_CLKOUT1p,PLL_2B_T_CLKOUT1,PLL_2B_T_FB1.BE61 (io), E41 DIFF_IO_2B_T16_N,PLL_2B_T_CLKOUT1n.BE57 (io), E42 DIFF_IO_2B_T22_N.BM49 (io), E43 DIFF_IO_2B_T22_P.BK49 (power), E44 DIFF_IO_2B_T13_N.BF46 (io), E45 DIFF_IO_2B_T13_P.BE46 (io), E46 DIFF_IO_2B_T4_P.CF28 (io), E47 DIFF_IO_2B_T4_N.CC28 (io), E48 GND (power), E49 GND (power), E50 GND (power), F01 GND (power), F02 DIFF_IO_2A_B6_N,CLK_B_2A_1n.BM92 (io), F03 DIFF_IO_2A_B6_P,CLK_B_2A_1p.BP92 (io), F04 DIFF_IO_2A_B4_N,PLL_2A_B_CLKOUT1n.BM89 (io), F05 DIFF_IO_2A_B4_P,PLL_2A_B_CLKOUT1p,PLL_2A_B_CLKOUT1,PLL_2A_B_FB1.BK89 (io), F06 DIFF_IO_2A_B2_P.BH81 (io), F07 DIFF_IO_2A_B2_N.BH78 (io), F08 GND (power), F09 DIFF_IO_2A_B9_N,PLL_2A_B_CLKOUT0n.BU81 (io), F10 DIFF_IO_2A_B9_P,PLL_2A_B_CLKOUT0p,PLL_2A_B_CLKOUT0,PLL_2A_B_FB0.BR81 (io), F11 GND (power), F12 DIFF_IO_2A_B17_P.CF92 (io), F13 DIFF_IO_2A_B17_N.CH92 (io), F14 GND (power), F15 DIFF_IO_2A_T6_P.CF71 (io), F16 DIFF_IO_2A_T6_N.CH71 (io), F17 GND (power), F18 GND (power), F19 DIFF_IO_2A_T4_N.CF69 (io), F20 DIFF_IO_2A_T4_P.CH69 (io), F21 GND (power), F22 GND (power), F23 DIFF_IO_2A_T8_N.BR59 (io), F24 DIFF_IO_2A_T8_P.BU59 (io), F25 GND (power), F26 GND (power), F27 DIFF_IO_2B_B23_P.CK73 (io), F28 DIFF_IO_2B_B23_N.CL73 (io), F29 GND (power), F30 GND (power), F31 DIFF_IO_2B_B20_P.CK56 (power), F32 DIFF_IO_2B_B20_N.CL54 (io), F33 DIFF_IO_2B_B18_N.CK45 (io), F34 DIFF_IO_2B_B18_P.CL42 (io), F35 GND (power), F36 DIFF_IO_2B_B14_P.CK33 (io), F37 DIFF_IO_2B_B14_N.CL30 (io), F38 GND (power), F39 DIFF_IO_2B_T21_P,PLL_2B_T_CLKOUT0p,PLL_2B_T_CLKOUT0,PLL_2B_T_FB0.BP41 (io), F40 DIFF_IO_2B_T21_N,PLL_2B_T_CLKOUT0n.BM41 (io), F41 GND (power), F42 DIFF_IO_2B_T9_N.CL11 (io), F43 DIFF_IO_2B_T9_P.CL14 (io), F44 GND (power), F45 DIFF_IO_2B_T11_N.CK20 (io), F46 DIFF_IO_2B_T11_P.CL20 (io), F47 GND (power), F48 DIFF_IO_2B_T5_P.CA31 (io), F49 DIFF_IO_2B_T5_N.CC31 (io), F50 GND (power)
part D pins: G01 VCCIO_2B (power), G02 VCCIO_2B (power), G03 DIFF_IO_2A_B23_N.CL97 (io), G04 DIFF_IO_2A_B23_P.CK97 (io), G05 GND (power), G06 DIFF_IO_2A_B22_N.CK88 (io), G07 DIFF_IO_2A_B22_P.CL88 (io), G08 GND (power), G09 DIFF_IO_2A_B18_N.CA92 (io), G10 DIFF_IO_2A_B18_P.CC92 (io), G11 DIFF_IO_2A_T18_P,CLK_T_2A_1p.BM71 (io), G12 DIFF_IO_2A_T18_N,CLK_T_2A_1n.BP71 (io), G13 DIFF_IO_2A_T22_N.BE86 (io), G14 DIFF_IO_2A_T22_P.BF86 (io), G15 GND (power), G16 GND (power), G17 GTSR4B_RX_CH0_P.BF1 (in), G18 GTSR4B_RX_CH0_N.BF3 (in), G19 GND (power), G20 GND (power), G21 GTSR4B_RX_CH1_P.BD1 (in), G22 GTSR4B_RX_CH1_N.BD3 (in), G23 GND (power), G24 GND (power), G25 GTSR4B_RX_CH2_P.BB1 (in), G26 GTSR4B_RX_CH2_N.BB3 (in), G27 GND (power), G28 GND (power), G29 GTSR4B_RX_CH3_P.AY1 (in), G30 GTSR4B_RX_CH3_N.AY3 (in), G31 GND (power), G32 DIFF_IO_2B_B19_N.CK54 (io), G33 DIFF_IO_2B_B19_P.CL51 (io), G34 DIFF_IO_2B_B15_N.CL35 (io), G35 DIFF_IO_2B_B15_P.CK35 (io), G36 GND (power), G37 DIFF_IO_2B_B13_P.CK30 (io), G38 DIFF_IO_2B_B13_N.CL26 (io), G39 GND (power), G40 DIFF_IO_2B_T8_N.CL8 (io), G41 DIFF_IO_2B_T8_P.CK11 (io), G42 GND (power), G43 DIFF_IO_2B_T12_P.CL23 (io), G44 DIFF_IO_2B_T12_N.CK26 (io), G45 GND (power), G46 DIFF_IO_2B_T3_N.CA22 (io), G47 DIFF_IO_2B_T3_P.CC22 (io), G48 GND (power), G49 DIFF_IO_2B_T1_P.CF19 (io), G50 DIFF_IO_2B_T1_N.CC19 (io), H01 FAN_EN (power), H02 GND (power), H03 DIFF_IO_2A_B24_N.CK94 (io), H04 DIFF_IO_2A_B24_P.CL91 (io), H05 GND (power), H06 DIFF_IO_2A_B21_N.CL85 (io), H07 DIFF_IO_2A_B21_P.CK85 (io), H08 GND (power), H09 DIFF_IO_2A_B20_N.CL82 (io), H10 DIFF_IO_2A_B20_P.CK80 (io), H11 GND (power), H12 DIFF_IO_2A_B19_P.CK76 (io), H13 DIFF_IO_2A_B19_N.CL76 (io), H14 GND (power), H15 REFCLK_GTSR4B_RX_P.AY16 (in), H16 REFCLK_GTSR4B_RX_N.AY21 (in), H17 GND (power), H18 GND (power), H19 GTSR4B_TX_CH0_P.BE7 (out), H20 GTSR4B_TX_CH0_N.BE10 (out), H21 GND (power), H22 GND (power), H23 GTSR4B_TX_CH1_P.BC7 (out), H24 GTSR4B_TX_CH1_N.BC10 (out), H25 GND (power), H26 GND (power), H27 GTSR4B_TX_CH2_P.BA7 (out), H28 GTSR4B_TX_CH2_N.BA10 (out), H29 GND (power), H30 GND (power), H31 GTSR4B_TX_CH3_P.AW7 (out), H32 GTSR4B_TX_CH3_N.AW10 (out), H33 GND (power), H34 GND (power), H35 REFCLK_GTSR4B_CH1_P.AV16 (in), H36 REFCLK_GTSR4B_CH1_N.AV21 (in), H37 GND (power), H38 DIFF_IO_2B_T18_N,CLK_T_2B_1n.BE68 (io), H39 DIFF_IO_2B_T18_P,CLK_T_2B_1p.BF68 (io), H40 GND (power), H41 DIFF_IO_2B_T23_N.BH52 (io), H42 DIFF_IO_2B_T23_P.BH49 (io), H43 GND (power), H44 DIFF_IO_2B_T14_P.BF50 (io), H45 DIFF_IO_2B_T14_N.BE50 (io), H46 GND (power), H47 DIFF_IO_2B_T2_N.CH22 (io), H48 DIFF_IO_2B_T2_P.CF22 (io), H49 DIFF_IO_2B_T6_P.CH31 (io), H50 DIFF_IO_2B_T6_N.CF31 (io)

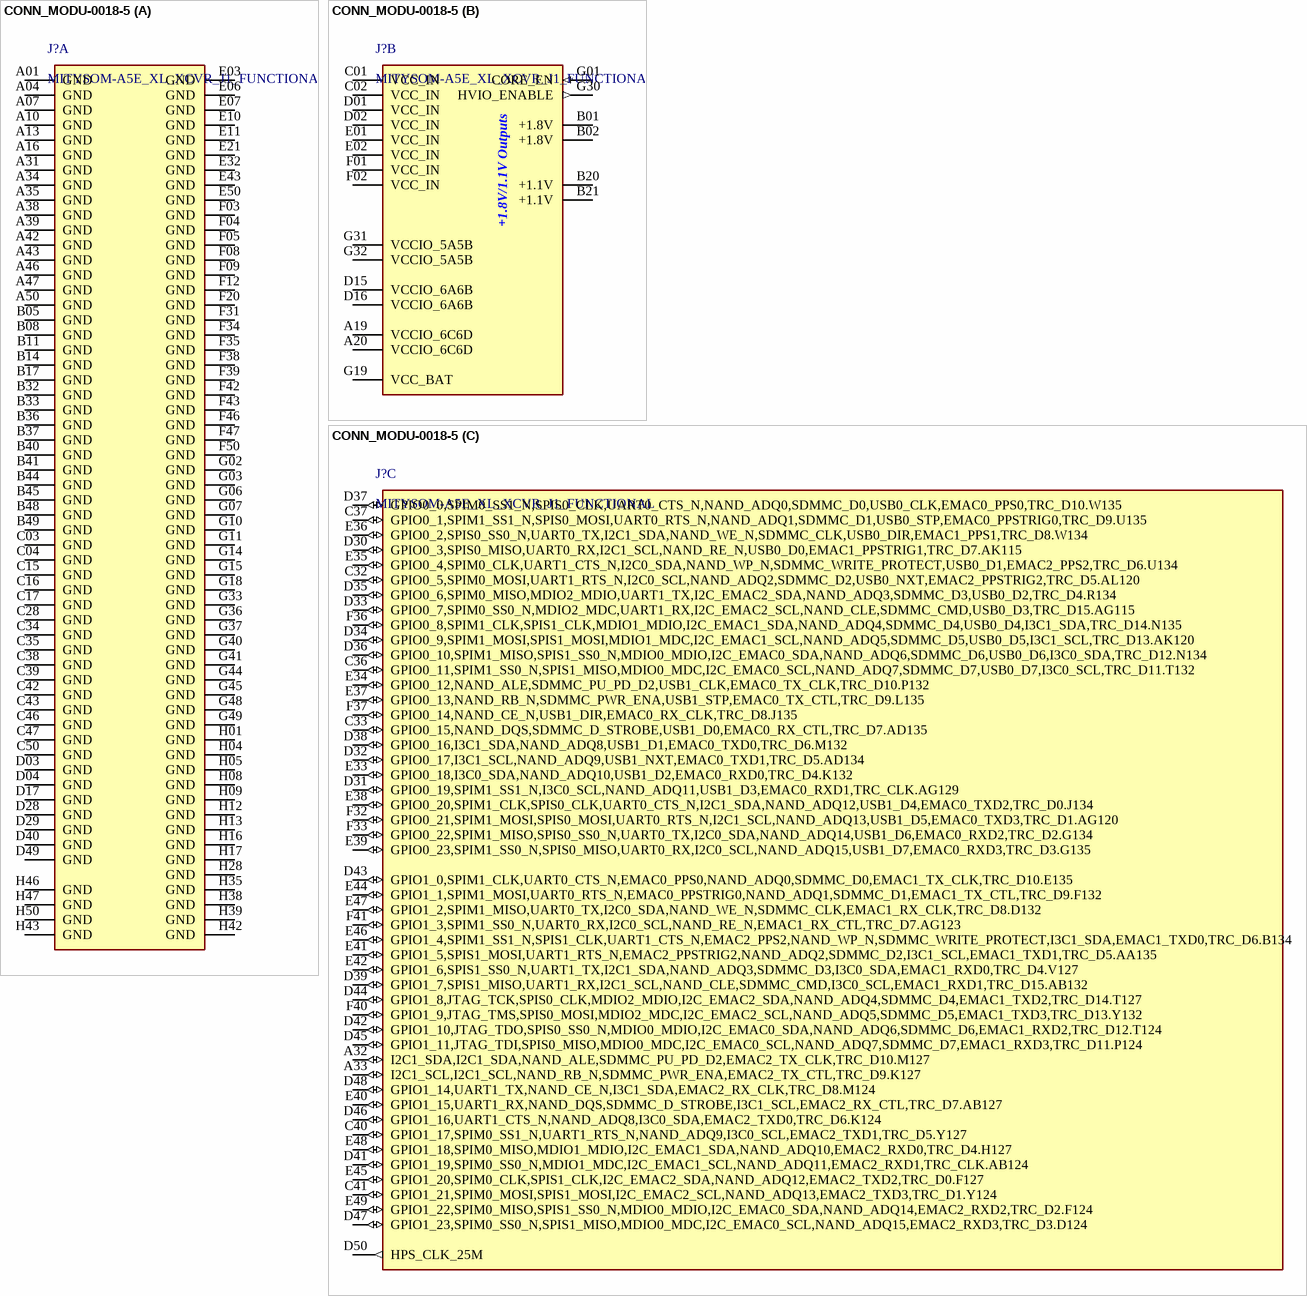
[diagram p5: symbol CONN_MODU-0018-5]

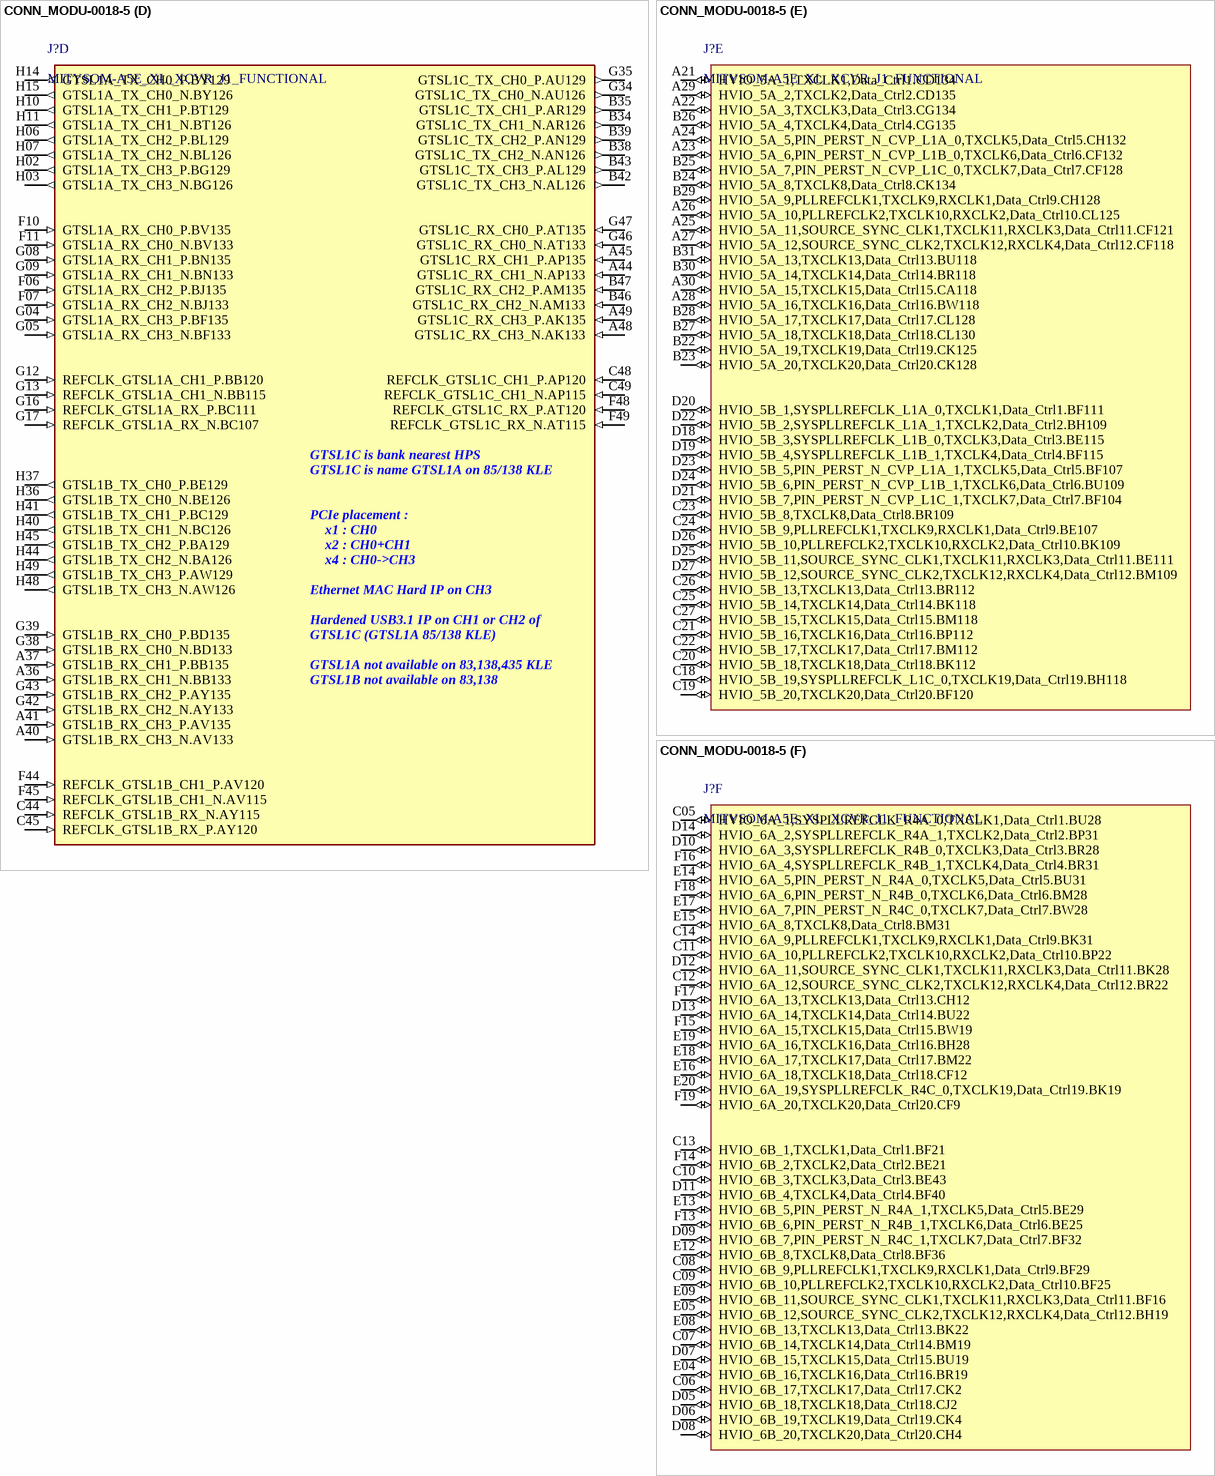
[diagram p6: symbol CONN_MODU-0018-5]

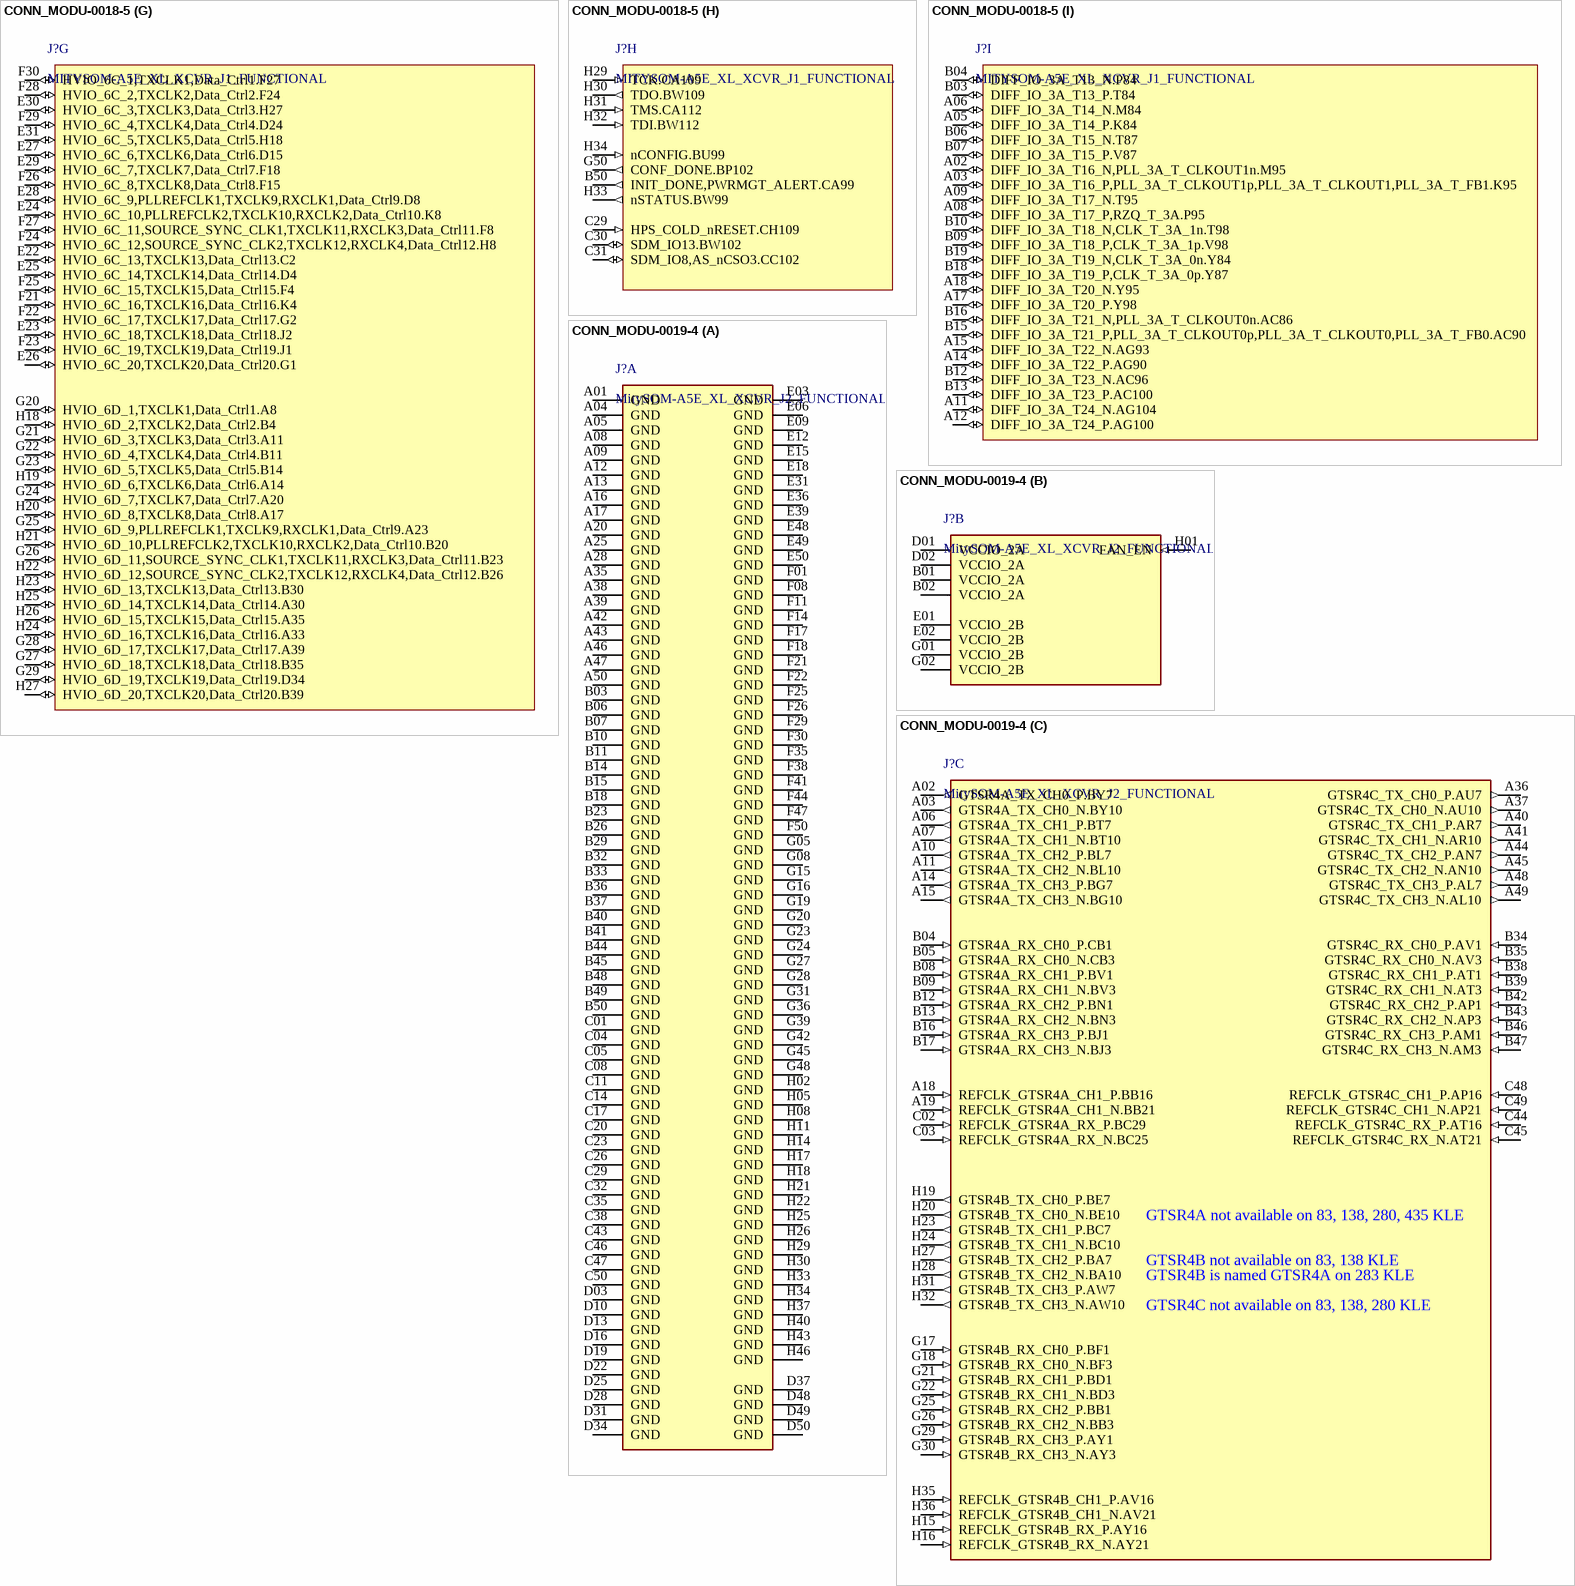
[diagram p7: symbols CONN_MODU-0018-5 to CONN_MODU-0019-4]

## CONN_MODU-0018-5
designator J?, comment MITYSOM-A5E_XL_XCVR_J1_FUNCTIONAL
MitySOM-A5E XL XCVR Interface Connector, J1 CONN HD ARRAY PLUG 400P SMD GOLD; Manuf 1_PN: SEAM-50-02.0-L-08-2-A-K-TR; Manuf 2_PN: SEAM-50-02.0-S-08-2-A-K-TR; Manuf 1: Samtec; Angle: Vertical; CLPN: 13059
footprint SEAM-50-02.0-S-08-2-A-K-TR_MitySOM_A5E_J1 (CONN ARRAY SOCKET 400 POS SMD, with mechanical guidelines MitySOM-A5E J1/J2)
part A pins: A01 GND (power), A04 GND (power), A07 GND (power), A10 GND (power), A13 GND (power), A16 GND (power), A31 GND (power), A34 GND (power), A35 GND (power), A38 GND (power), A39 GND (power), A42 GND (power), A43 GND (power), A46 GND (power), A47 GND (power), A50 GND (power), B05 GND (power), B08 GND (power), B11 GND (power), B14 GND (power), B17 GND (power), B32 GND (power), B33 GND (power), B36 GND (power), B37 GND (power), B40 GND (power), B41 GND (power), B44 GND (power), B45 GND (power), B48 GND (power), B49 GND (power), C03 GND (power), C04 GND (power), C15 GND (power), C16 GND (power), C17 GND (power), C28 GND (power), C34 GND (power), C35 GND (power), C38 GND (power), C39 GND (power), C42 GND (power), C43 GND (power), C46 GND (power), C47 GND (power), C50 GND (power), D03 GND (power), D04 GND (power), D17 GND (power), D28 GND (power), D29 GND (power), D40 GND (power), D49 GND (power), E03 GND (power), E06 GND (power), E07 GND (power), E10 GND (power), E11 GND (power), E21 GND (power), E32 GND (power), E43 GND (power), E50 GND (power), F03 GND (power), F04 GND (power), F05 GND (power), F08 GND (power), F09 GND (power), F12 GND (power), F20 GND (power), F31 GND (power), F34 GND (power), F35 GND (power), F38 GND (power), F39 GND (power), F42 GND (power), F43 GND (power), F46 GND (power), F47 GND (power), F50 GND (power), G02 GND (power), G03 GND (power), G06 GND (power), G07 GND (power), G10 GND (power), G11 GND (power), G14 GND (power), G15 GND (power), G18 GND (power), G33 GND (power), G36 GND (power), G37 GND (power), G40 GND (power), G41 GND (power), G44 GND (power), G45 GND (power), G48 GND (power), G49 GND (power), H01 GND (power), H04 GND (power), H05 GND (power), H08 GND (power), H09 GND (power), H12 GND (power), H13 GND (power), H16 GND (power), H17 GND (power), H28 GND (power), H35 GND (power), H38 GND (power), H39 GND (power), H42 GND (power), H43 GND (power), H46 GND (power), H47 GND (power), H50 GND (power)
part B pins: A19 VCCIO_6C6D (power), A20 VCCIO_6C6D (power), B01 +1.8V (power), B02 +1.8V (power), B20 +1.1V (power), B21 +1.1V (power), C01 VCC_IN (power), C02 VCC_IN (power), D01 VCC_IN (power), D02 VCC_IN (power), D15 VCCIO_6A6B (power), D16 VCCIO_6A6B (power), E01 VCC_IN (power), E02 VCC_IN (power), F01 VCC_IN (power), F02 VCC_IN (power), G01 CORE_EN (in), G19 VCC_BAT (power), G30 HVIO_ENABLE (out), G31 VCCIO_5A5B (power), G32 VCCIO_5A5B (power)
part C pins: A32 I2C1_SDA,I2C1_SDA,NAND_ALE,SDMMC_PU_PD_D2,EMAC2_TX_CLK,TRC_D10.M127 (io), A33 I2C1_SCL,I2C1_SCL,NAND_RB_N,SDMMC_PWR_ENA,EMAC2_TX_CTL,TRC_D9.K127 (io), C32 GPIO0_5,SPIM0_MOSI,UART1_RTS_N,I2C0_SCL,NAND_ADQ2,SDMMC_D2,USB0_NXT,EMAC2_PPSTRIG2,TRC_D5.AL120 (io), C33 GPIO0_15,NAND_DQS,SDMMC_D_STROBE,USB1_D0,EMAC0_RX_CTL,TRC_D7.AD135 (io), C36 GPIO0_11,SPIM1_SS0_N,SPIS1_MISO,MDIO0_MDC,I2C_EMAC0_SCL,NAND_ADQ7,SDMMC_D7,USB0_D7,I3C0_SCL,TRC_D11.T132 (io), C37 GPIO0_1,SPIM1_SS1_N,SPIS0_MOSI,UART0_RTS_N,NAND_ADQ1,SDMMC_D1,USB0_STP,EMAC0_PPSTRIG0,TRC_D9.U135 (io), C40 GPIO1_17,SPIM0_SS1_N,UART1_RTS_N,NAND_ADQ9,I3C0_SCL,EMAC2_TXD1,TRC_D5.Y127 (io), C41 GPIO1_21,SPIM0_MOSI,SPIS1_MOSI,I2C_EMAC2_SCL,NAND_ADQ13,EMAC2_TXD3,TRC_D1.Y124 (io), D30 GPIO0_3,SPIS0_MISO,UART0_RX,I2C1_SCL,NAND_RE_N,USB0_D0,EMAC1_PPSTRIG1,TRC_D7.AK115 (io), D31 GPIO0_19,SPIM1_SS1_N,I3C0_SCL,NAND_ADQ11,USB1_D3,EMAC0_RXD1,TRC_CLK.AG129 (io), D32 GPIO0_17,I3C1_SCL,NAND_ADQ9,USB1_NXT,EMAC0_TXD1,TRC_D5.AD134 (io), D33 GPIO0_7,SPIM0_SS0_N,MDIO2_MDC,UART1_RX,I2C_EMAC2_SCL,NAND_CLE,SDMMC_CMD,USB0_D3,TRC_D15.AG115 (io), D34 GPIO0_9,SPIM1_MOSI,SPIS1_MOSI,MDIO1_MDC,I2C_EMAC1_SCL,NAND_ADQ5,SDMMC_D5,USB0_D5,I3C1_SCL,TRC_D13.AK120 (io), D35 GPIO0_6,SPIM0_MISO,MDIO2_MDIO,UART1_TX,I2C_EMAC2_SDA,NAND_ADQ3,SDMMC_D3,USB0_D2,TRC_D4.R134 (io), D36 GPIO0_10,SPIM1_MISO,SPIS1_SS0_N,MDIO0_MDIO,I2C_EMAC0_SDA,NAND_ADQ6,SDMMC_D6,USB0_D6,I3C0_SDA,TRC_D12.N134 (io), D37 GPIO0_0,SPIM0_SS1_N,SPIS0_CLK,UART0_CTS_N,NAND_ADQ0,SDMMC_D0,USB0_CLK,EMAC0_PPS0,TRC_D10.W135 (io), D38 GPIO0_16,I3C1_SDA,NAND_ADQ8,USB1_D1,EMAC0_TXD0,TRC_D6.M132 (io), D39 GPIO1_7,SPIS1_MISO,UART1_RX,I2C1_SCL,NAND_CLE,SDMMC_CMD,I3C0_SCL,EMAC1_RXD1,TRC_D15.AB132 (io), D41 GPIO1_19,SPIM0_SS0_N,MDIO1_MDC,I2C_EMAC1_SCL,NAND_ADQ11,EMAC2_RXD1,TRC_CLK.AB124 (io), D42 GPIO1_10,JTAG_TDO,SPIS0_SS0_N,MDIO0_MDIO,I2C_EMAC0_SDA,NAND_ADQ6,SDMMC_D6,EMAC1_RXD2,TRC_D12.T124 (io), D43 GPIO1_0,SPIM1_CLK,UART0_CTS_N,EMAC0_PPS0,NAND_ADQ0,SDMMC_D0,EMAC1_TX_CLK,TRC_D10.E135 (io), D44 GPIO1_8,JTAG_TCK,SPIS0_CLK,MDIO2_MDIO,I2C_EMAC2_SDA,NAND_ADQ4,SDMMC_D4,EMAC1_TXD2,TRC_D14.T127 (io), D45 GPIO1_11,JTAG_TDI,SPIS0_MISO,MDIO0_MDC,I2C_EMAC0_SCL,NAND_ADQ7,SDMMC_D7,EMAC1_RXD3,TRC_D11.P124 (io), D46 GPIO1_16,UART1_CTS_N,NAND_ADQ8,I3C0_SDA,EMAC2_TXD0,TRC_D6.K124 (io), D47 GPIO1_23,SPIM0_SS0_N,SPIS1_MISO,MDIO0_MDC,I2C_EMAC0_SCL,NAND_ADQ15,EMAC2_RXD3,TRC_D3.D124 (io), D48 GPIO1_14,UART1_TX,NAND_CE_N,I3C1_SDA,EMAC2_RX_CLK,TRC_D8.M124 (io), D50 HPS_CLK_25M (out) "25 MHz Clock output to be tied to HPS IO pin.", E33 GPIO0_18,I3C0_SDA,NAND_ADQ10,USB1_D2,EMAC0_RXD0,TRC_D4.K132 (io), E34 GPIO0_12,NAND_ALE,SDMMC_PU_PD_D2,USB1_CLK,EMAC0_TX_CLK,TRC_D10.P132 (io), E35 GPIO0_4,SPIM0_CLK,UART1_CTS_N,I2C0_SDA,NAND_WP_N,SDMMC_WRITE_PROTECT,USB0_D1,EMAC2_PPS2,TRC_D6.U134 (io), E36 GPIO0_2,SPIS0_SS0_N,UART0_TX,I2C1_SDA,NAND_WE_N,SDMMC_CLK,USB0_DIR,EMAC1_PPS1,TRC_D8.W134 (io), E37 GPIO0_13,NAND_RB_N,SDMMC_PWR_ENA,USB1_STP,EMAC0_TX_CTL,TRC_D9.L135 (io), E38 GPIO0_20,SPIM1_CLK,SPIS0_CLK,UART0_CTS_N,I2C1_SDA,NAND_ADQ12,USB1_D4,EMAC0_TXD2,TRC_D0.J134 (io), E39 GPIO0_23,SPIM1_SS0_N,SPIS0_MISO,UART0_RX,I2C0_SCL,NAND_ADQ15,USB1_D7,EMAC0_RXD3,TRC_D3.G135 (io), E40 GPIO1_15,UART1_RX,NAND_DQS,SDMMC_D_STROBE,I3C1_SCL,EMAC2_RX_CTL,TRC_D7.AB127 (io), E41 GPIO1_5,SPIS1_MOSI,UART1_RTS_N,EMAC2_PPSTRIG2,NAND_ADQ2,SDMMC_D2,I3C1_SCL,EMAC1_TXD1,TRC_D5.AA135 (io), E42 GPIO1_6,SPIS1_SS0_N,UART1_TX,I2C1_SDA,NAND_ADQ3,SDMMC_D3,I3C0_SDA,EMAC1_RXD0,TRC_D4.V127 (io), E44 GPIO1_1,SPIM1_MOSI,UART0_RTS_N,EMAC0_PPSTRIG0,NAND_ADQ1,SDMMC_D1,EMAC1_TX_CTL,TRC_D9.F132 (io), E45 GPIO1_20,SPIM0_CLK,SPIS1_CLK,I2C_EMAC2_SDA,NAND_ADQ12,EMAC2_TXD2,TRC_D0.F127 (io), E46 GPIO1_4,SPIM1_SS1_N,SPIS1_CLK,UART1_CTS_N,EMAC2_PPS2,NAND_WP_N,SDMMC_WRITE_PROTECT,I3C1_SDA,EMAC1_TXD0,TRC_D6.B134 (io), E47 GPIO1_2,SPIM1_MISO,UART0_TX,I2C0_SDA,NAND_WE_N,SDMMC_CLK,EMAC1_RX_CLK,TRC_D8.D132 (io), E48 GPIO1_18,SPIM0_MISO,MDIO1_MDIO,I2C_EMAC1_SDA,NAND_ADQ10,EMAC2_RXD0,TRC_D4.H127 (io), E49 GPIO1_22,SPIM0_MISO,SPIS1_SS0_N,MDIO0_MDIO,I2C_EMAC0_SDA,NAND_ADQ14,EMAC2_RXD2,TRC_D2.F124 (io), F32 GPIO0_21,SPIM1_MOSI,SPIS0_MOSI,UART0_RTS_N,I2C1_SCL,NAND_ADQ13,USB1_D5,EMAC0_TXD3,TRC_D1.AG120 (io), F33 GPIO0_22,SPIM1_MISO,SPIS0_SS0_N,UART0_TX,I2C0_SDA,NAND_ADQ14,USB1_D6,EMAC0_RXD2,TRC_D2.G134 (io), F36 GPIO0_8,SPIM1_CLK,SPIS1_CLK,MDIO1_MDIO,I2C_EMAC1_SDA,NAND_ADQ4,SDMMC_D4,USB0_D4,I3C1_SDA,TRC_D14.N135 (io), F37 GPIO0_14,NAND_CE_N,USB1_DIR,EMAC0_RX_CLK,TRC_D8.J135 (io), F40 GPIO1_9,JTAG_TMS,SPIS0_MOSI,MDIO2_MDC,I2C_EMAC2_SCL,NAND_ADQ5,SDMMC_D5,EMAC1_TXD3,TRC_D13.Y132 (io), F41 GPIO1_3,SPIM1_SS0_N,UART0_RX,I2C0_SCL,NAND_RE_N,EMAC1_RX_CTL,TRC_D7.AG123 (io)
part D pins: A36 GTSL1B_RX_CH1_N.BB133 (in), A37 GTSL1B_RX_CH1_P.BB135 (in), A40 GTSL1B_RX_CH3_N.AV133 (in), A41 GTSL1B_RX_CH3_P.AV135 (in), A44 GTSL1C_RX_CH1_N.AP133 (in), A45 GTSL1C_RX_CH1_P.AP135 (in), A48 GTSL1C_RX_CH3_N.AK133 (in), A49 GTSL1C_RX_CH3_P.AK135 (in), B34 GTSL1C_TX_CH1_N.AR126 (out), B35 GTSL1C_TX_CH1_P.AR129 (out), B38 GTSL1C_TX_CH2_N.AN126 (out), B39 GTSL1C_TX_CH2_P.AN129 (out), B42 GTSL1C_TX_CH3_N.AL126 (out), B43 GTSL1C_TX_CH3_P.AL129 (out), B46 GTSL1C_RX_CH2_N.AM133 (in), B47 GTSL1C_RX_CH2_P.AM135 (in), C44 REFCLK_GTSL1B_RX_N.AY115 (in), C45 REFCLK_GTSL1B_RX_P.AY120 (in), C48 REFCLK_GTSL1C_CH1_P.AP120 (in), C49 REFCLK_GTSL1C_CH1_N.AP115 (in), F06 GTSL1A_RX_CH2_P.BJ135 (in), F07 GTSL1A_RX_CH2_N.BJ133 (in), F10 GTSL1A_RX_CH0_P.BV135 (in), F11 GTSL1A_RX_CH0_N.BV133 (in), F44 REFCLK_GTSL1B_CH1_P.AV120 (in), F45 REFCLK_GTSL1B_CH1_N.AV115 (in), F48 REFCLK_GTSL1C_RX_P.AT120 (in), F49 REFCLK_GTSL1C_RX_N.AT115 (in), G04 GTSL1A_RX_CH3_P.BF135 (in), G05 GTSL1A_RX_CH3_N.BF133 (in), G08 GTSL1A_RX_CH1_P.BN135 (in), G09 GTSL1A_RX_CH1_N.BN133 (in), G12 REFCLK_GTSL1A_CH1_P.BB120 (in), G13 REFCLK_GTSL1A_CH1_N.BB115 (in), G16 REFCLK_GTSL1A_RX_P.BC111 (in), G17 REFCLK_GTSL1A_RX_N.BC107 (in), G34 GTSL1C_TX_CH0_N.AU126 (out), G35 GTSL1C_TX_CH0_P.AU129 (out), G38 GTSL1B_RX_CH0_N.BD133 (in), G39 GTSL1B_RX_CH0_P.BD135 (in), G42 GTSL1B_RX_CH2_N.AY133 (in), G43 GTSL1B_RX_CH2_P.AY135 (in), G46 GTSL1C_RX_CH0_N.AT133 (in), G47 GTSL1C_RX_CH0_P.AT135 (in), H02 GTSL1A_TX_CH3_P.BG129 (out), H03 GTSL1A_TX_CH3_N.BG126 (out), H06 GTSL1A_TX_CH2_P.BL129 (out), H07 GTSL1A_TX_CH2_N.BL126 (out), H10 GTSL1A_TX_CH1_P.BT129 (out), H11 GTSL1A_TX_CH1_N.BT126 (out), H14 GTSL1A_TX_CH0_P.BY129 (out), H15 GTSL1A_TX_CH0_N.BY126 (out), H36 GTSL1B_TX_CH0_N.BE126 (out), H37 GTSL1B_TX_CH0_P.BE129 (out), H40 GTSL1B_TX_CH1_N.BC126 (out), H41 GTSL1B_TX_CH1_P.BC129 (out), H44 GTSL1B_TX_CH2_N.BA126 (out), H45 GTSL1B_TX_CH2_P.BA129 (out), H48 GTSL1B_TX_CH3_N.AW126 (out), H49 GTSL1B_TX_CH3_P.AW129 (out)
part E pins: A21 HVIO_5A_1,TXCLK1,Data_Ctrl1.CD134 (io), A22 HVIO_5A_3,TXCLK3,Data_Ctrl3.CG134 (io), A23 HVIO_5A_6,PIN_PERST_N_CVP_L1B_0,TXCLK6,Data_Ctrl6.CF132 (io), A24 HVIO_5A_5,PIN_PERST_N_CVP_L1A_0,TXCLK5,Data_Ctrl5.CH132 (io), A25 HVIO_5A_11,SOURCE_SYNC_CLK1,TXCLK11,RXCLK3,Data_Ctrl11.CF121 (io), A26 HVIO_5A_10,PLLREFCLK2,TXCLK10,RXCLK2,Data_Ctrl10.CL125 (io), A27 HVIO_5A_12,SOURCE_SYNC_CLK2,TXCLK12,RXCLK4,Data_Ctrl12.CF118 (io), A28 HVIO_5A_16,TXCLK16,Data_Ctrl16.BW118 (io), A29 HVIO_5A_2,TXCLK2,Data_Ctrl2.CD135 (io), A30 HVIO_5A_15,TXCLK15,Data_Ctrl15.CA118 (io), B22 HVIO_5A_19,TXCLK19,Data_Ctrl19.CK125 (io), B23 HVIO_5A_20,TXCLK20,Data_Ctrl20.CK128 (io), B24 HVIO_5A_8,TXCLK8,Data_Ctrl8.CK134 (io), B25 HVIO_5A_7,PIN_PERST_N_CVP_L1C_0,TXCLK7,Data_Ctrl7.CF128 (io), B26 HVIO_5A_4,TXCLK4,Data_Ctrl4.CG135 (io), B27 HVIO_5A_18,TXCLK18,Data_Ctrl18.CL130 (io), B28 HVIO_5A_17,TXCLK17,Data_Ctrl17.CL128 (io), B29 HVIO_5A_9,PLLREFCLK1,TXCLK9,RXCLK1,Data_Ctrl9.CH128 (io), B30 HVIO_5A_14,TXCLK14,Data_Ctrl14.BR118 (io), B31 HVIO_5A_13,TXCLK13,Data_Ctrl13.BU118 (io), C18 HVIO_5B_19,SYSPLLREFCLK_L1C_0,TXCLK19,Data_Ctrl19.BH118 (io), C19 HVIO_5B_20,TXCLK20,Data_Ctrl20.BF120 (io), C20 HVIO_5B_18,TXCLK18,Data_Ctrl18.BK112 (io), C21 HVIO_5B_16,TXCLK16,Data_Ctrl16.BP112 (io), C22 HVIO_5B_17,TXCLK17,Data_Ctrl17.BM112 (io), C23 HVIO_5B_8,TXCLK8,Data_Ctrl8.BR109 (io), C24 HVIO_5B_9,PLLREFCLK1,TXCLK9,RXCLK1,Data_Ctrl9.BE107 (io), C25 HVIO_5B_14,TXCLK14,Data_Ctrl14.BK118 (io), C26 HVIO_5B_13,TXCLK13,Data_Ctrl13.BR112 (io), C27 HVIO_5B_15,TXCLK15,Data_Ctrl15.BM118 (io), D18 HVIO_5B_3,SYSPLLREFCLK_L1B_0,TXCLK3,Data_Ctrl3.BE115 (io), D19 HVIO_5B_4,SYSPLLREFCLK_L1B_1,TXCLK4,Data_Ctrl4.BF115 (io), D20 HVIO_5B_1,SYSPLLREFCLK_L1A_0,TXCLK1,Data_Ctrl1.BF111 (io), D21 HVIO_5B_7,PIN_PERST_N_CVP_L1C_1,TXCLK7,Data_Ctrl7.BF104 (io), D22 HVIO_5B_2,SYSPLLREFCLK_L1A_1,TXCLK2,Data_Ctrl2.BH109 (io), D23 HVIO_5B_5,PIN_PERST_N_CVP_L1A_1,TXCLK5,Data_Ctrl5.BF107 (io), D24 HVIO_5B_6,PIN_PERST_N_CVP_L1B_1,TXCLK6,Data_Ctrl6.BU109 (io), D25 HVIO_5B_11,SOURCE_SYNC_CLK1,TXCLK11,RXCLK3,Data_Ctrl11.BE111 (io), D26 HVIO_5B_10,PLLREFCLK2,TXCLK10,RXCLK2,Data_Ctrl10.BK109 (io), D27 HVIO_5B_12,SOURCE_SYNC_CLK2,TXCLK12,RXCLK4,Data_Ctrl12.BM109 (io)
part F pins: C05 HVIO_6A_1,SYSPLLREFCLK_R4A_0,TXCLK1,Data_Ctrl1.BU28 (io), C06 HVIO_6B_17,TXCLK17,Data_Ctrl17.CK2 (io), C07 HVIO_6B_14,TXCLK14,Data_Ctrl14.BM19 (io), C08 HVIO_6B_9,PLLREFCLK1,TXCLK9,RXCLK1,Data_Ctrl9.BF29 (io), C09 HVIO_6B_10,PLLREFCLK2,TXCLK10,RXCLK2,Data_Ctrl10.BF25 (io), C10 HVIO_6B_3,TXCLK3,Data_Ctrl3.BE43 (io), C11 HVIO_6A_10,PLLREFCLK2,TXCLK10,RXCLK2,Data_Ctrl10.BP22 (io), C12 HVIO_6A_12,SOURCE_SYNC_CLK2,TXCLK12,RXCLK4,Data_Ctrl12.BR22 (io), C13 HVIO_6B_1,TXCLK1,Data_Ctrl1.BF21 (io), C14 HVIO_6A_9,PLLREFCLK1,TXCLK9,RXCLK1,Data_Ctrl9.BK31 (io), D05 HVIO_6B_18,TXCLK18,Data_Ctrl18.CJ2 (io), D06 HVIO_6B_19,TXCLK19,Data_Ctrl19.CK4 (io), D07 HVIO_6B_15,TXCLK15,Data_Ctrl15.BU19 (io), D08 HVIO_6B_20,TXCLK20,Data_Ctrl20.CH4 (io), D09 HVIO_6B_7,PIN_PERST_N_R4C_1,TXCLK7,Data_Ctrl7.BF32 (io), D10 HVIO_6A_3,SYSPLLREFCLK_R4B_0,TXCLK3,Data_Ctrl3.BR28 (io), D11 HVIO_6B_4,TXCLK4,Data_Ctrl4.BF40 (io), D12 HVIO_6A_11,SOURCE_SYNC_CLK1,TXCLK11,RXCLK3,Data_Ctrl11.BK28 (io), D13 HVIO_6A_14,TXCLK14,Data_Ctrl14.BU22 (io), D14 HVIO_6A_2,SYSPLLREFCLK_R4A_1,TXCLK2,Data_Ctrl2.BP31 (io), E04 HVIO_6B_16,TXCLK16,Data_Ctrl16.BR19 (io), E05 HVIO_6B_12,SOURCE_SYNC_CLK2,TXCLK12,RXCLK4,Data_Ctrl12.BH19 (io), E08 HVIO_6B_13,TXCLK13,Data_Ctrl13.BK22 (io), E09 HVIO_6B_11,SOURCE_SYNC_CLK1,TXCLK11,RXCLK3,Data_Ctrl11.BF16 (io), E12 HVIO_6B_8,TXCLK8,Data_Ctrl8.BF36 (io), E13 HVIO_6B_5,PIN_PERST_N_R4A_1,TXCLK5,Data_Ctrl5.BE29 (io), E14 HVIO_6A_5,PIN_PERST_N_R4A_0,TXCLK5,Data_Ctrl5.BU31 (io), E15 HVIO_6A_8,TXCLK8,Data_Ctrl8.BM31 (io), E16 HVIO_6A_18,TXCLK18,Data_Ctrl18.CF12 (io), E17 HVIO_6A_7,PIN_PERST_N_R4C_0,TXCLK7,Data_Ctrl7.BW28 (io), E18 HVIO_6A_17,TXCLK17,Data_Ctrl17.BM22 (io), E19 HVIO_6A_16,TXCLK16,Data_Ctrl16.BH28 (io), E20 HVIO_6A_19,SYSPLLREFCLK_R4C_0,TXCLK19,Data_Ctrl19.BK19 (io), F13 HVIO_6B_6,PIN_PERST_N_R4B_1,TXCLK6,Data_Ctrl6.BE25 (io), F14 HVIO_6B_2,TXCLK2,Data_Ctrl2.BE21 (io), F15 HVIO_6A_15,TXCLK15,Data_Ctrl15.BW19 (io), F16 HVIO_6A_4,SYSPLLREFCLK_R4B_1,TXCLK4,Data_Ctrl4.BR31 (io), F17 HVIO_6A_13,TXCLK13,Data_Ctrl13.CH12 (io), F18 HVIO_6A_6,PIN_PERST_N_R4B_0,TXCLK6,Data_Ctrl6.BM28 (io), F19 HVIO_6A_20,TXCLK20,Data_Ctrl20.CF9 (io)
part G pins: E22 HVIO_6C_13,TXCLK13,Data_Ctrl13.C2 (io), E23 HVIO_6C_18,TXCLK18,Data_Ctrl18.J2 (io), E24 HVIO_6C_10,PLLREFCLK2,TXCLK10,RXCLK2,Data_Ctrl10.K8 (io), E25 HVIO_6C_14,TXCLK14,Data_Ctrl14.D4 (io), E26 HVIO_6C_20,TXCLK20,Data_Ctrl20.G1 (io), E27 HVIO_6C_6,TXCLK6,Data_Ctrl6.D15 (io), E28 HVIO_6C_9,PLLREFCLK1,TXCLK9,RXCLK1,Data_Ctrl9.D8 (io), E29 HVIO_6C_7,TXCLK7,Data_Ctrl7.F18 (io), E30 HVIO_6C_3,TXCLK3,Data_Ctrl3.H27 (io), E31 HVIO_6C_5,TXCLK5,Data_Ctrl5.H18 (io), F21 HVIO_6C_16,TXCLK16,Data_Ctrl16.K4 (io), F22 HVIO_6C_17,TXCLK17,Data_Ctrl17.G2 (io), F23 HVIO_6C_19,TXCLK19,Data_Ctrl19.J1 (io), F24 HVIO_6C_12,SOURCE_SYNC_CLK2,TXCLK12,RXCLK4,Data_Ctrl12.H8 (io), F25 HVIO_6C_15,TXCLK15,Data_Ctrl15.F4 (io), F26 HVIO_6C_8,TXCLK8,Data_Ctrl8.F15 (io), F27 HVIO_6C_11,SOURCE_SYNC_CLK1,TXCLK11,RXCLK3,Data_Ctrl11.F8 (io), F28 HVIO_6C_2,TXCLK2,Data_Ctrl2.F24 (io), F29 HVIO_6C_4,TXCLK4,Data_Ctrl4.D24 (io), F30 HVIO_6C_1,TXCLK1,Data_Ctrl1.F27 (io), G20 HVIO_6D_1,TXCLK1,Data_Ctrl1.A8 (io), G21 HVIO_6D_3,TXCLK3,Data_Ctrl3.A11 (io), G22 HVIO_6D_4,TXCLK4,Data_Ctrl4.B11 (io), G23 HVIO_6D_5,TXCLK5,Data_Ctrl5.B14 (io), G24 HVIO_6D_7,TXCLK7,Data_Ctrl7.A20 (io), G25 HVIO_6D_9,PLLREFCLK1,TXCLK9,RXCLK1,Data_Ctrl9.A23 (io), G26 HVIO_6D_11,SOURCE_SYNC_CLK1,TXCLK11,RXCLK3,Data_Ctrl11.B23 (io), G27 HVIO_6D_18,TXCLK18,Data_Ctrl18.B35 (io), G28 HVIO_6D_17,TXCLK17,Data_Ctrl17.A39 (io), G29 HVIO_6D_19,TXCLK19,Data_Ctrl19.D34 (io), H18 HVIO_6D_2,TXCLK2,Data_Ctrl2.B4 (io), H19 HVIO_6D_6,TXCLK6,Data_Ctrl6.A14 (io), H20 HVIO_6D_8,TXCLK8,Data_Ctrl8.A17 (io), H21 HVIO_6D_10,PLLREFCLK2,TXCLK10,RXCLK2,Data_Ctrl10.B20 (io), H22 HVIO_6D_12,SOURCE_SYNC_CLK2,TXCLK12,RXCLK4,Data_Ctrl12.B26 (io), H23 HVIO_6D_13,TXCLK13,Data_Ctrl13.B30 (io), H24 HVIO_6D_16,TXCLK16,Data_Ctrl16.A33 (io), H25 HVIO_6D_14,TXCLK14,Data_Ctrl14.A30 (io), H26 HVIO_6D_15,TXCLK15,Data_Ctrl15.A35 (io), H27 HVIO_6D_20,TXCLK20,Data_Ctrl20.B39 (io)
part H pins: B50 INIT_DONE,PWRMGT_ALERT.CA99 (out), C29 HPS_COLD_nRESET.CH109 (in), C30 SDM_IO13.BW102 (io), C31 SDM_IO8,AS_nCSO3.CC102 (io), G50 CONF_DONE.BP102 (out), H29 TCK.CA109 (in), H30 TDO.BW109 (out), H31 TMS.CA112 (in), H32 TDI.BW112 (in), H33 nSTATUS.BW99 (out), H34 nCONFIG.BU99 (in)
part I pins: A02 DIFF_IO_3A_T16_N,PLL_3A_T_CLKOUT1n.M95 (io), A03 DIFF_IO_3A_T16_P,PLL_3A_T_CLKOUT1p,PLL_3A_T_CLKOUT1,PLL_3A_T_FB1.K95 (io), A05 DIFF_IO_3A_T14_P.K84 (io), A06 DIFF_IO_3A_T14_N.M84 (io), A08 DIFF_IO_3A_T17_P,RZQ_T_3A.P95 (io), A09 DIFF_IO_3A_T17_N.T95 (io), A11 DIFF_IO_3A_T24_N.AG104 (io), A12 DIFF_IO_3A_T24_P.AG100 (io), A14 DIFF_IO_3A_T22_P.AG90 (io), A15 DIFF_IO_3A_T22_N.AG93 (io), A17 DIFF_IO_3A_T20_P.Y98 (io), A18 DIFF_IO_3A_T20_N.Y95 (io), B03 DIFF_IO_3A_T13_P.T84 (io), B04 DIFF_IO_3A_T13_N.P84 (io), B06 DIFF_IO_3A_T15_N.T87 (io), B07 DIFF_IO_3A_T15_P.V87 (io), B09 DIFF_IO_3A_T18_P,CLK_T_3A_1p.V98 (io), B10 DIFF_IO_3A_T18_N,CLK_T_3A_1n.T98 (io), B12 DIFF_IO_3A_T23_N.AC96 (io), B13 DIFF_IO_3A_T23_P.AC100 (io), B15 DIFF_IO_3A_T21_P,PLL_3A_T_CLKOUT0p,PLL_3A_T_CLKOUT0,PLL_3A_T_FB0.AC90 (io), B16 DIFF_IO_3A_T21_N,PLL_3A_T_CLKOUT0n.AC86 (io), B18 DIFF_IO_3A_T19_P,CLK_T_3A_0p.Y87 (io), B19 DIFF_IO_3A_T19_N,CLK_T_3A_0n.Y84 (io)

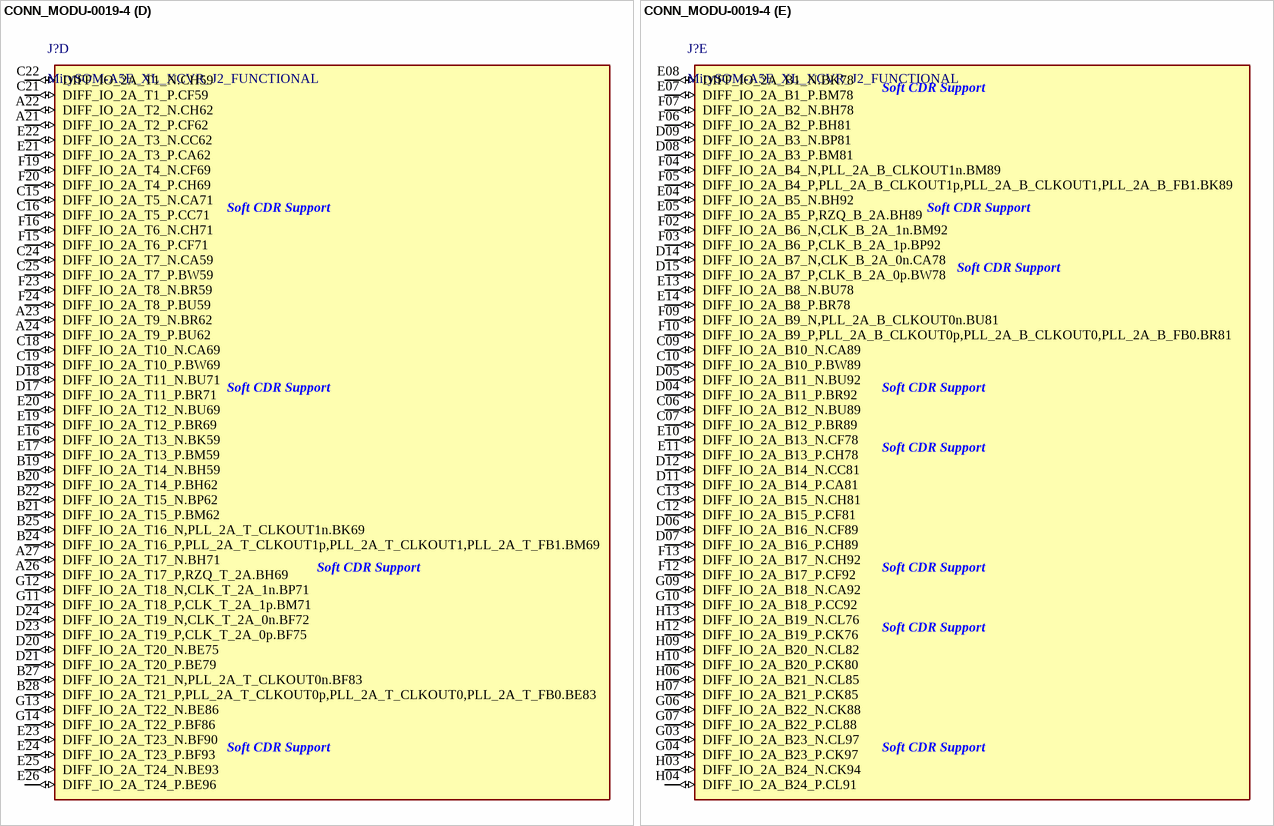
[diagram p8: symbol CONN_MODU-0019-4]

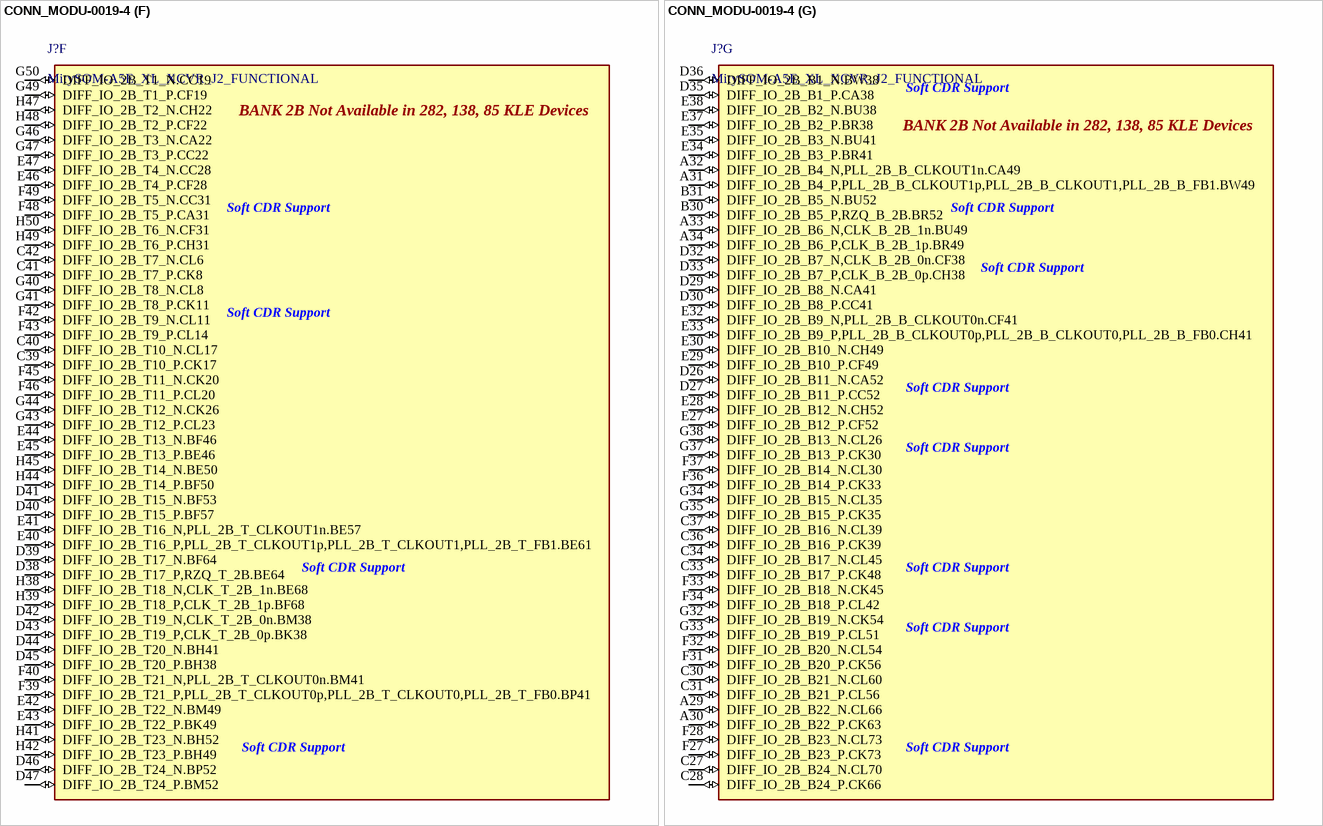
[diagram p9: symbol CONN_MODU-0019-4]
